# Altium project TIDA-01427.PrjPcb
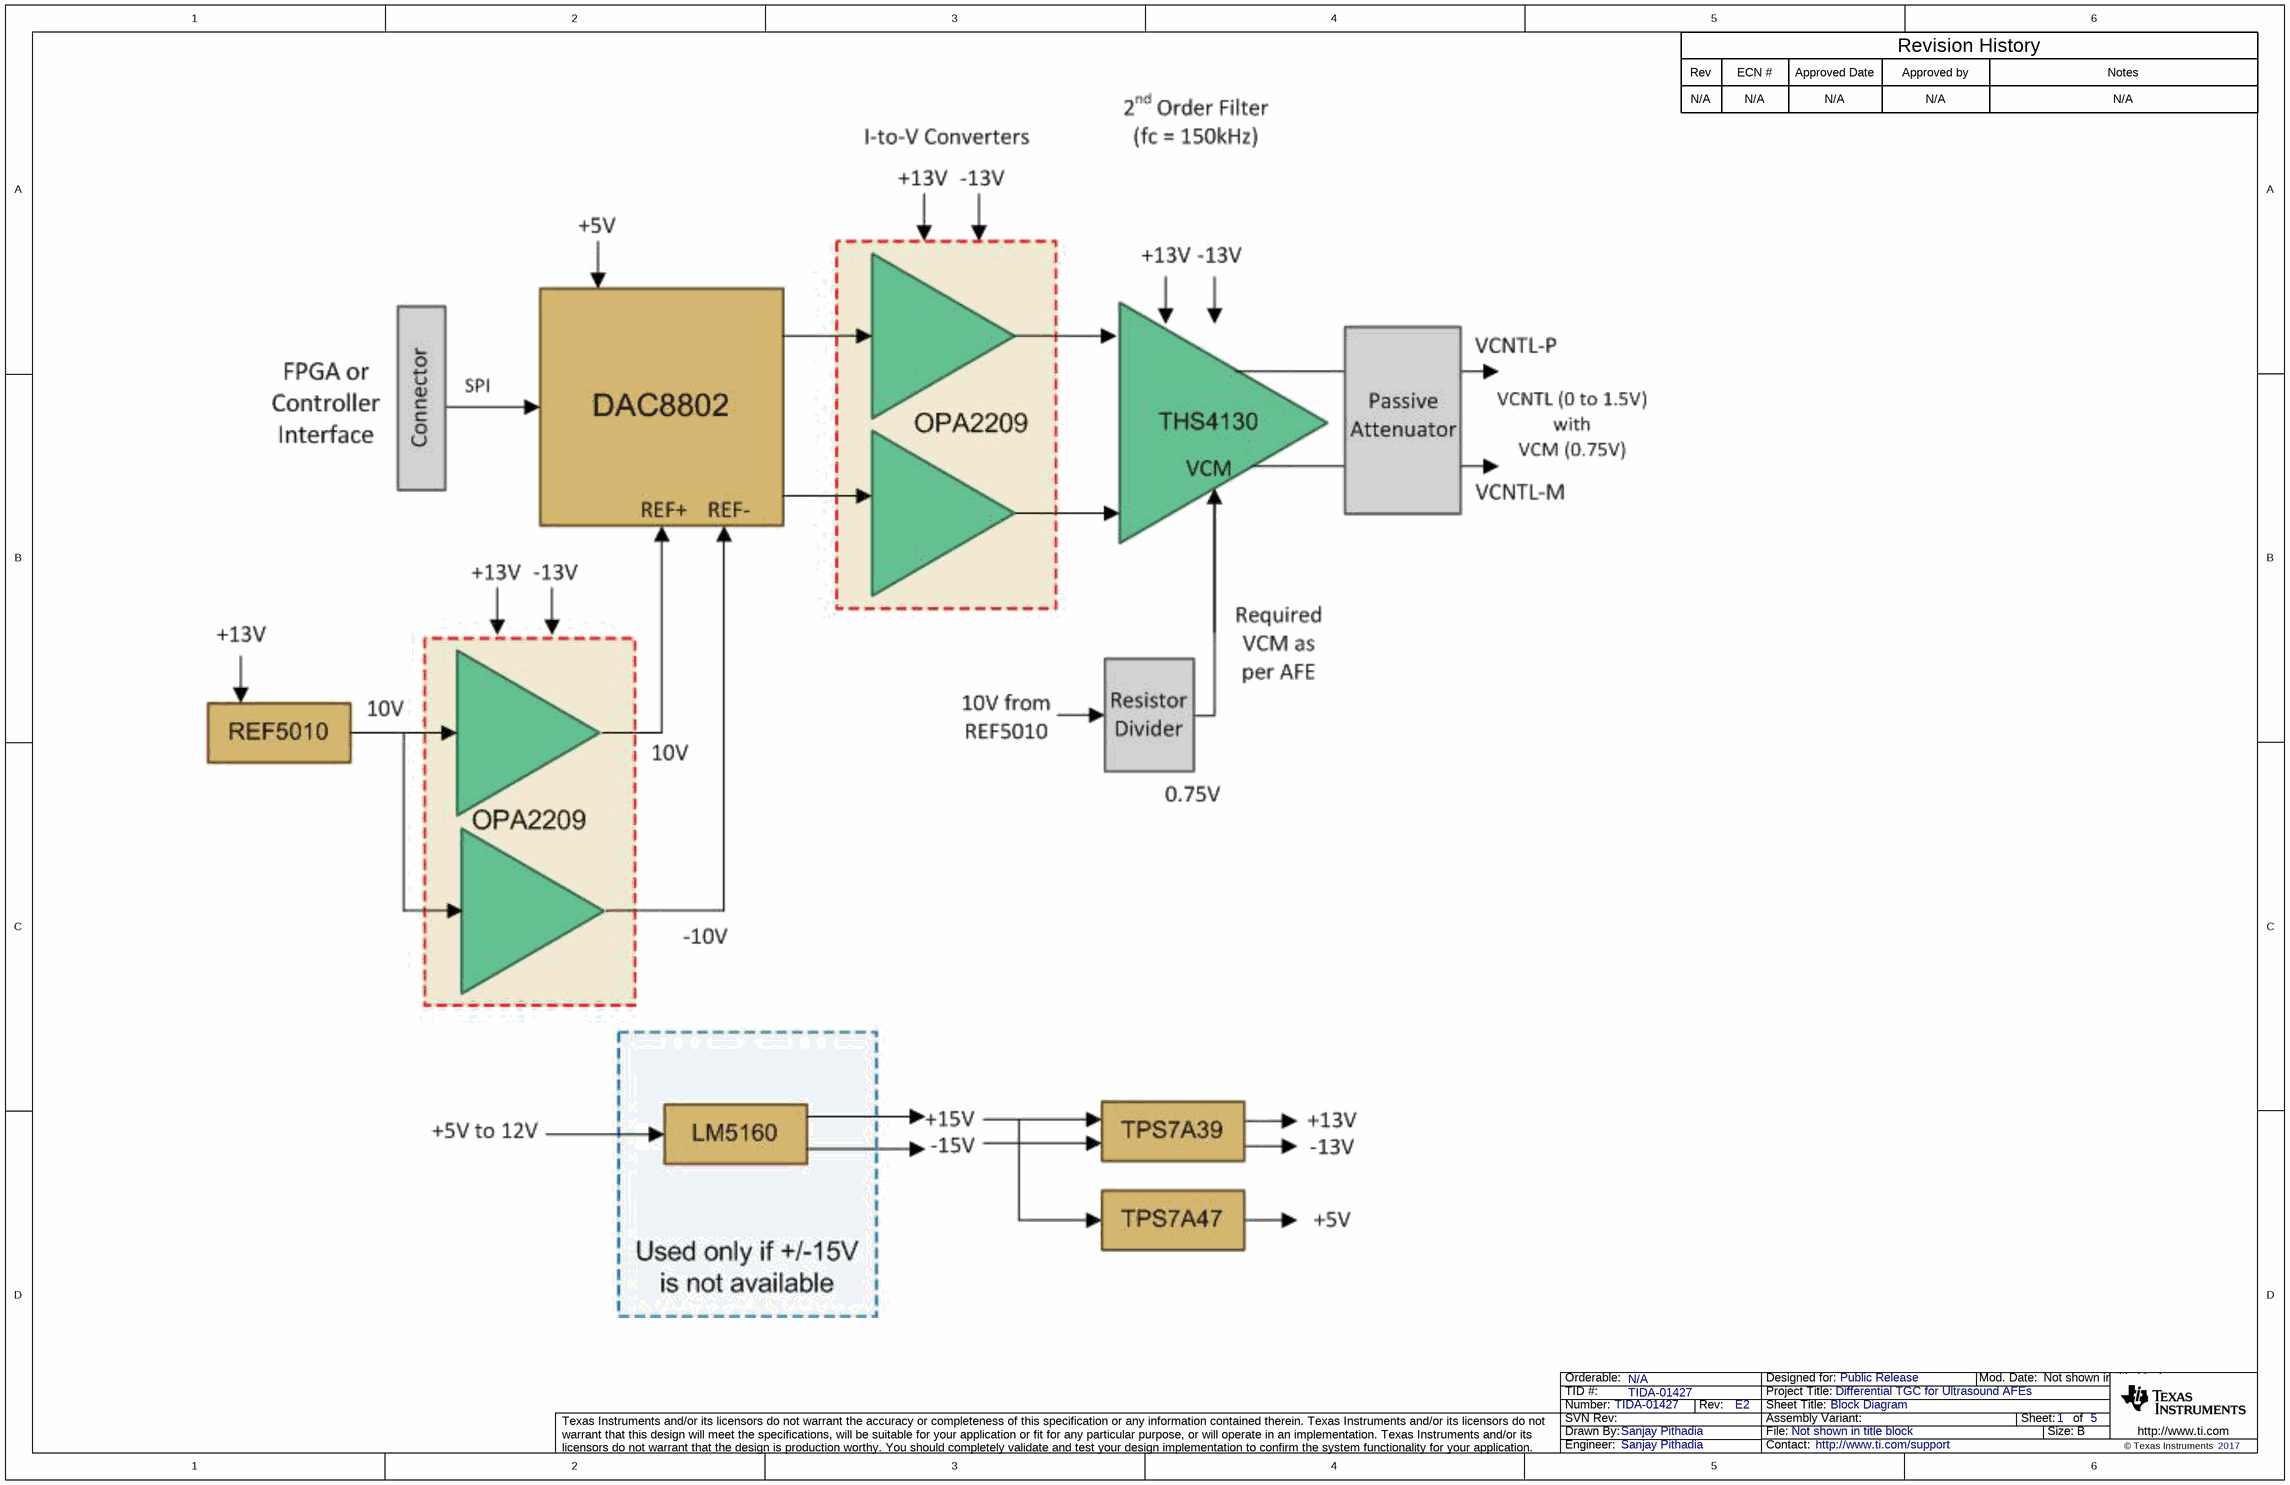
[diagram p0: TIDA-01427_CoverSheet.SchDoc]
CopyrightYear: 2017; EVM_orderable: N/A; PCB_Layout: Akshay Labhe; PCB_Rev: E2; PRJ_Customer: Public Release; PRJ_Engineer: Sanjay Pithadia; PRJ_Number: TIDA-01427; PRJ_Title: Differential TGC for Ultrasound AFEs; SCH_Rev: E2; TechSupport: http://www.ti.com/support; TID: TIDA-01427
5 sheets, 175 parts. Net scope: flat (ports and power ports of the same name join across sheets).
Board file: TIDA-01427_PCB.PcbDoc
Sheets:
  TIDA-01427_CoverSheet.SchDoc
  TIDA-01427_Power_Supply.SchDoc
  TIDA-01427_Reference.SchDoc
  TIDA-01427_DAC_I2V_Filter_Attenuator.SchDoc
  TIDA-01427_Hardware.SchDoc

## Sheet TIDA-01427_CoverSheet.SchDoc: Block Diagram
size 431 x 279 mm; Date: Not shown in title block; ApprovedBy: Not shown in title block; CheckedBy: Not shown in title block; Author: Not shown in title block; CompanyName: Not shown in title block; DrawnBy: Sanjay Pithadia; Engineer: Not shown in title block; Organization: Not shown in title block; Address1: Not shown in title block; Address2: Not shown in title block; Address3: Not shown in title block; Address4: Not shown in title block; DocumentNumber: 1; Revision: Use project parameter SCH_Rev; SheetNumber: 1; SheetTotal: 5; PageSetup: Record=PageOptions¦CenterHorizontal=True¦CenterVertical=True¦PrintScale=1.00¦XCorrection=1.00¦YCorrection=1.00¦PrintKind=0¦BorderSize=5000000¦LeftOffset=0¦BottomOffset=0¦Orientation=2¦PaperLength=1000¦PaperWidth=1000¦Scale=100¦PaperSource=15¦PrintQuality=600¦MediaType=1¦DitherType=10¦PaperKind=Letter¦PrintScaleMode=1

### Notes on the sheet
- Rev
- N/A
- ECN #
- Approved Date
- Approved by
- Revision History
- Notes

## Sheet TIDA-01427_Power_Supply.SchDoc: Power Supply
size 431 x 279 mm; Date: Not shown in title block; ApprovedBy: Not shown in title block; CheckedBy: Not shown in title block; Author: Not shown in title block; CompanyName: Not shown in title block; DrawnBy: Sanjay Pithadia; Engineer: Not shown in title block; Organization: Not shown in title block; Address1: Not shown in title block; Address2: Not shown in title block; Address3: Not shown in title block; Address4: Not shown in title block; DocumentNumber: 1; Revision: Use project parameter SCH_Rev; SheetNumber: 2; SheetTotal: 5; PageSetup: Record=PageOptions¦CenterHorizontal=True¦CenterVertical=True¦PrintScale=1.00¦XCorrection=1.00¦YCorrection=1.00¦PrintKind=0¦BorderSize=5000000¦LeftOffset=0¦BottomOffset=0¦Orientation=2¦PaperLength=1000¦PaperWidth=1000¦Scale=100¦PaperSource=15¦PrintQuality=600¦MediaType=1¦DitherType=10¦PaperKind=Letter¦PrintScaleMode=1
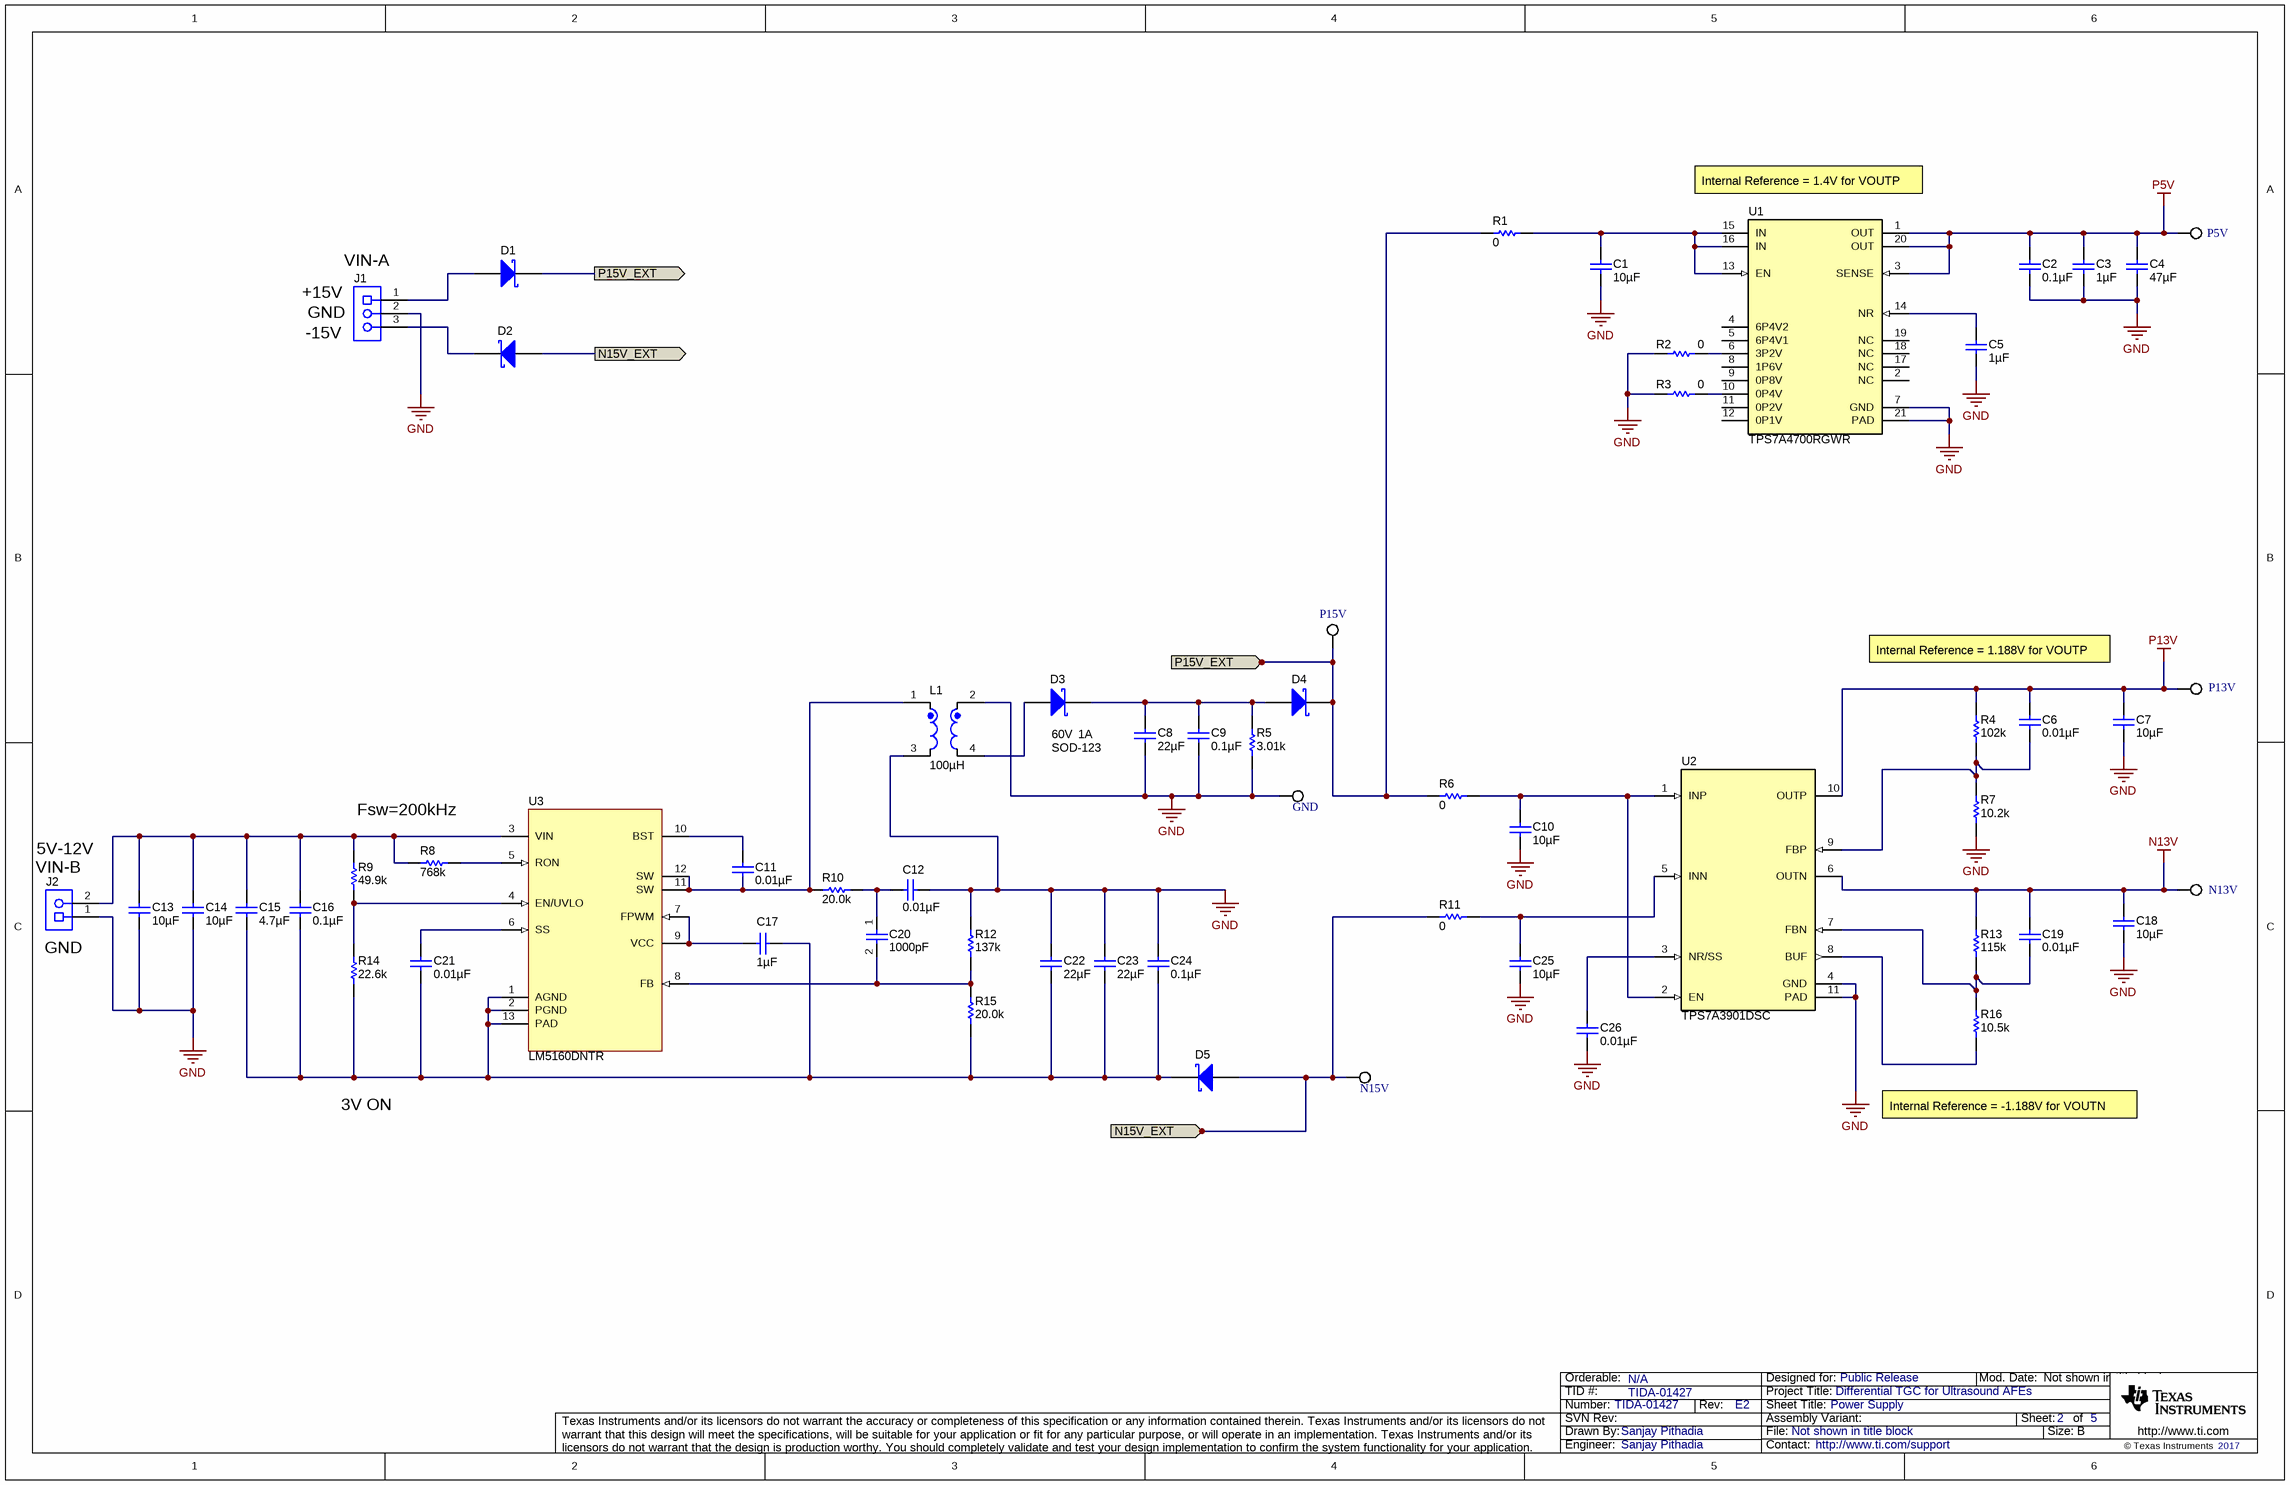
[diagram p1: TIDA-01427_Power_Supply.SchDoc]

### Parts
C1  ValueDisplayed: 10µF  [1210_270]  (hidden comment: GRM32ER71H106KA12L)
C2  ValueDisplayed: 0.1µF  [0603]  (hidden comment: GCM188R71H104KA57D)
C3  ValueDisplayed: 1µF  [0603]  (hidden comment: GRM188R61H105KAALD)
C4  ValueDisplayed: 47µF  [1210_270]  (hidden comment: GRM32EC81C476ME15L)
C5  ValueDisplayed: 1µF  [0603]  (hidden comment: GRM188R61H105KAALD)
C6  ValueDisplayed: 0.01µF  [0603]  (hidden comment: C0603C103J5RACTU)
C7  ValueDisplayed: 10µF  [1210_270]  (hidden comment: GRM32ER71H106KA12L)
C8  ValueDisplayed: 22µF  [1210L]  (hidden comment: GRM32ER71E226KE15L)
C9  ValueDisplayed: 0.1µF  [0603]  (hidden comment: GCM188R71H104KA57D)
C10  ValueDisplayed: 10µF  [1210_270]  (hidden comment: GRM32ER71H106KA12L)
C11  ValueDisplayed: 0.01µF  [0603]  (hidden comment: C0603C103J5RACTU)
C12  ValueDisplayed: 0.01µF  [0603]  (hidden comment: C0603C103J5RACTU)
C13  ValueDisplayed: 10µF  [1210_270]  (hidden comment: GRM32ER71H106KA12L)
C14  ValueDisplayed: 10µF  [1210_270]  (hidden comment: GRM32ER71H106KA12L)
C15  ValueDisplayed: 4.7µF  [1206]  (hidden comment: GRM319R61E475KA12D)
C16  ValueDisplayed: 0.1µF  [0603L]  (hidden comment: C1608X7R1H104K)
C17  ValueDisplayed: 1µF  [0603L]  (hidden comment: C1608X7R1E105K080AB)
C18  ValueDisplayed: 10µF  [1210_270]  (hidden comment: GRM32ER71H106KA12L)
C19  ValueDisplayed: 0.01µF  [0603]  (hidden comment: C0603C103J5RACTU)
C20  ValueDisplayed: 1000pF  [0603]  (hidden comment: GRM188R71H102JA01D)
C21  ValueDisplayed: 0.01µF  [0603]  (hidden comment: C0603C103J5RACTU)
C22  ValueDisplayed: 22µF  [1210L]  (hidden comment: GRM32ER71E226KE15L)
C23  ValueDisplayed: 22µF  [1210L]
C24  ValueDisplayed: 0.1µF  [0603]  (hidden comment: GCM188R71H104KA57D)
C25  ValueDisplayed: 10µF  [1210_270]  (hidden comment: GRM32ER71H106KA12L)
C26  ValueDisplayed: 0.01µF  [0603]  (hidden comment: C0603C103J5RACTU)
D1  DFLS130L-7  [PowerDI123]  (value not drawn)
D2  DFLS130L-7  [PowerDI123]  (value not drawn)
D3  value 60V  Value1: 1A  [SOD-123]  (hidden comment: RB160M-60TR)
D4  DFLS130L-7  [PowerDI123]  (value not drawn)
D5  DFLS130L-7  [PowerDI123]  (value not drawn)
GND  5007  [Keystone5007]  (value not drawn)
J1  ED555/3DS  [TERM_BLK_ED555-3DS]  (value not drawn)
J2  39357-0002  [Molex_39357-0002]  (value not drawn)
L1  ValueDisplayed: 100µH  [SRF1260]  (hidden comment: SRF1260-101M)
N13V  5007  [Keystone5007]  (value not drawn)
N15V  5007  [Keystone5007]  (value not drawn)
P5V  5007  [Keystone5007]  (value not drawn)
P13V  5007  [Keystone5007]  (value not drawn)
P15V  5007  [Keystone5007]  (value not drawn)
R1  ValueDisplayed: 0  [0603]  (hidden comment: CRCW06030000Z0EA)
R2  ValueDisplayed: 0  [0603]  (hidden comment: CRCW06030000Z0EA)
R3  ValueDisplayed: 0  [0603]  (hidden comment: CRCW06030000Z0EA)
R4  ValueDisplayed: 102k  [0603]  (hidden comment: CRCW0603102KFKEA)
R5  ValueDisplayed: 3.01k  [0603L]  (hidden comment: CRCW06033K01FKEA)
R6  ValueDisplayed: 0  [0603]  (hidden comment: CRCW06030000Z0EA)
R7  ValueDisplayed: 10.2k  [0603]  (hidden comment: RC0603FR-0710K2L)
R8  ValueDisplayed: 768k  [0603L]  (hidden comment: CRCW0603768KFKEA)
R9  ValueDisplayed: 49.9k  [0603L]  (hidden comment: CRCW060349K9FKEA)
R10  ValueDisplayed: 20.0k  [0603L]  (hidden comment: CRCW060320K0FKEA)
R11  ValueDisplayed: 0  [0603]  (hidden comment: CRCW06030000Z0EA)
R12  ValueDisplayed: 137k  [0603]  (hidden comment: CRCW0603137KFKEA)
R13  ValueDisplayed: 115k  [0603]  (hidden comment: CRCW0603115KFKEA)
R14  ValueDisplayed: 22.6k  [0603L]  (hidden comment: CRCW060322K6FKEA)
R15  ValueDisplayed: 20.0k  [0603L]  (hidden comment: CRCW060320K0FKEA)
R16  ValueDisplayed: 10.5k  [0603]  (hidden comment: RC0603FR-0710K5L)
U1  TPS7A4700RGWR  [RGW0020A]
U2  TPS7A3901DSC  [DSC0010J]
U3  LM5160DNTR  [DNT0012B]

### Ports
N15V_EXT (in), N15V_EXT (out), P15V_EXT (in), P15V_EXT (out)

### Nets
GND: C1.2 C2.2 C3.2 C4.2 C5.2 C7.2 C8.2 C9.2 C10.2 C12.2 C13.2 C14.2 C18.2 C22.1 C23.1 C24.1 C25.2 C26.1 GND.1 J1.2 J2.1 L1.2 L1.3 R2.1 R3.1 R5.1 R7.1 R12.2 U1.7(GND) U1.21(PAD) U2.4(GND) U2.11(PAD)
N13V: C18.1 C19.2 N13V.1 R13.2 U2.6(OUTN)
P5V: C2.1 C3.1 C4.1 P5V.1 U1.1(OUT) U1.3(SENSE) U1.20(OUT)
P13V: C6.2 C7.1 P13V.1 R4.2 U2.10(OUTP)
N15V_EXT: D2.2(A) D5.2(A) N15V.1 R11.2 ; port N15V_EXT
P15V_EXT: D1.1(K) D4.1(K) P15V.1 R1.2 R6.2 ; port P15V_EXT
NetC1_1: C1.1 R1.1 U1.13(EN) U1.15(IN) U1.16(IN)
NetC5_1: C5.1 U1.14(NR)
NetC6_1: C6.1 R4.1 R7.2 U2.9(FBP)
NetC8_1: C8.1 C9.1 D3.1(K) D4.2(A) R5.2
NetC10_1: C10.1 R6.1 U2.1(INP) U2.2(EN)
NetC11_1: C11.1 U3.10(BST)
NetC11_2: C11.2 L1.1 R10.1 U3.11(SW) U3.12(SW)
NetC12_1: C12.1 C20.1 R10.2
NetC13_1: C13.1 C14.1 C15.1 C16.1 J2.2 R8.1 R9.2 U3.3(VIN)
NetC15_2: C15.2 C16.2 C17.1 C21.2 C22.2 C23.2 C24.2 D5.1(K) R14.1 R15.1 U3.1(AGND) U3.2(PGND) U3.13(PAD)
NetC17_2: C17.2 U3.7(FPWM) U3.9(VCC)
NetC19_1: C19.1 R13.1 R16.2 U2.7(FBN)
NetC20_2: C20.2 R12.1 R15.2 U3.8(FB)
NetC21_1: C21.1 U3.6(SS)
NetC25_1: C25.1 R11.1 U2.5(INN)
NetC26_2: C26.2 U2.3(NR/SS)
NetD1_2: D1.2(A) J1.1
NetD2_1: D2.1(K) J1.3
NetD3_2: D3.2(A) L1.4
NetR2_2: R2.2 U1.6(3P2V)
NetR3_2: R3.2 U1.10(0P4V)
NetR8_2: R8.2 U3.5(RON)
NetR9_1: R9.1 R14.2 U3.4(EN/UVLO)
NetR16_1: R16.1 U2.8(BUF)

Not connected (* = marked no-connect by the designer): U1 2(NC) 4(6P4V2) 5(6P4V1) 8(1P6V) 9(0P8V) 11(0P2V) 12(0P1V) 17(NC) 18(NC) 19(NC)

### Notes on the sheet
- (near U1) Internal Reference = 1.4V for VOUTP
- (near J1) +15V
- (near J1) VIN-A
- (near J1) -15V
- (near J1) GND
- Internal Reference = 1.188V for VOUTP
- Fsw=200kHz
- (near J2) VIN-B
- 5V-12V
- (near J2) GND
- 3V ON
- Internal Reference = -1.188V for VOUTN

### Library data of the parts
C1 C7 C10 C13 C14 C18 C25 = GRM32ER71H106KA12L: CAP, CERM, 10 µF, 50 V, +/- 10%, X7R, 1210; Manufacturer: MuRata; Polarized: N; CompType: Capacitor; Value: 10uF; U/M: EA; Cap_F: 0.00001; Tolerance_%: 10; Value1: Unknown; VDC_V: 50; Value2: 50V; TaMin_C: -55; TaMax_C: 125; Cap_Case: 1210; SizeArea_mm2: 8; SizeAreaWB_mm2: 14.7; SizeX_mm: 3.2; SizeY_mm: 2.5; SizeZ_mm: 2.7; AEC Category: Q200
C2 C9 C24 = GCM188R71H104KA57D: CAP, CERM, 0.1 µF, 50 V, +/- 10%, X7R, 0603; Manufacturer: MuRata; Polarized: N; CompType: Capacitor; Value: 0.1uF; U/M: EA; Cap_F: 0.0000001; Tolerance_%: 10; ESR_ohm: 0.02; Value1: 0.02 ohm; VDC_V: 50; Value2: 50V; IRMS_A: 1.84; TaMin_C: -55; TaMax_C: 125; SizeArea_mm2: 1.28; SizeAreaWB_mm2: 4.68; SizeX_mm: 1.6; SizeY_mm: 0.8; SizeZ_mm: 1; AEC Category: Q200
C3 C5 = GRM188R61H105KAALD: CAP, CERM, 1 µF, 50 V, +/- 10%, X5R, 0603; Manufacturer: MuRata; Polarized: N; CompType: Capacitor; Value: 1uF; U/M: EA; Cap_F: 0.000001; Tolerance_%: 10; Value1: Unknown; VDC_V: 50; Value2: 50V; TaMin_C: -55; TaMax_C: 85; SizeArea_mm2: 1.28; SizeAreaWB_mm2: 4.68; SizeX_mm: 1.6; SizeY_mm: 0.8; SizeZ_mm: 1; AEC Category: Q200
C4 = GRM32EC81C476ME15L: CAP, CERM, 47 µF, 16 V, +/- 20%, X6S, 1210; Manufacturer: MuRata; Polarized: N; CompType: Capacitor; Value: 47uF; U/M: EA; Cap_F: 0.000047; Tolerance_%: 20; Value1: Unknown; VDC_V: 16; Value2: 16V; TaMin_C: -55; TaMax_C: 105; Cap_Case: 1210; SizeArea_mm2: 8; SizeAreaWB_mm2: 14.7; SizeX_mm: 3.2; SizeY_mm: 2.5; SizeZ_mm: 2.7; AEC Category: Q200
C6 C11 C12 C19 C21 C26 = C0603C103J5RACTU: CAP, CERM, 0.01 µF, 50 V, +/- 5%, X7R, 0603; Manufacturer: Kemet; Polarized: N; CompType: Capacitor; Value: 0.01uF; U/M: EA; Cap_F: 0.00000001; Tolerance_%: 5; Value1: Unknown; VDC_V: 50; Value2: 50V; TaMin_C: -55; TaMax_C: 125; SizeArea_mm2: 1.28; SizeAreaWB_mm2: 4.68; SizeX_mm: 1.6; SizeY_mm: 0.8; SizeZ_mm: 1; AEC Category: Q200
C8 C22 C23 = GRM32ER71E226KE15L: CAP, CERM, 22uF, 25V, +/-10%, X7R, 1210; Manufacturer: MuRata; Polarized: N; CompType: Capacitor; U/M: EA; Cap_F: 0.000022; Tolerance_%: 10; Value1: Unknown; VDC_V: 25; TaMin_C: -55; TaMax_C: 125; Cap_Case: 1210
C15 = GRM319R61E475KA12D: CAP, CERM, 4.7 µF, 25 V, +/- 10%, X5R, 1206; Manufacturer: MuRata; Polarized: N; CompType: Capacitor; Value: 4.7uF; U/M: EA; Cap_F: 0.0000047; Tolerance_%: 10; ESR_ohm: 0.006; Value1: 0.006 ohm; VDC_V: 25; Value2: 25V; TaMin_C: -55; TaMax_C: 85; SizeArea_mm2: 5.12; SizeAreaWB_mm2: 10.92; SizeX_mm: 3.2; SizeY_mm: 1.6; SizeZ_mm: 1.35; AEC Category: Q200
C16 = C1608X7R1H104K: CAP, CERM, 0.1uF, 50V, +/-10%, X7R, 0603; Manufacturer: TDK; Polarized: N; CompType: Capacitor; U/M: EA; Cap_F: 0.0000001; Tolerance_%: 10; ESR_Ohm: 0.017; Value1: 0.017 ohm; VDC_V: 50; TaMin_C: -55; TaMax_C: 125; Cap_Case: 0603
C17 = C1608X7R1E105K080AB: CAP, CERM, 1uF, 25V, +/-10%, X7R, 0603; Manufacturer: TDK; Polarized: N; CompType: Capacitor; U/M: EA; Cap_F: 0.000001; Tolerance_%: 10; Value1: Unknown; VDC_V: 25; TaMin_C: -55; TaMax_C: 125; Cap_Case: 0603
C20 = GRM188R71H102JA01D: CAP, CERM, 1000 pF, 50 V, +/- 5%, X7R, 0603; Manufacturer: MuRata; Polarized: N; CompType: Capacitor; Value: 1000pF; U/M: EA; Cap_F: 0.000000001; Tolerance_%: 5; Value1: Unknown; VDC_V: 50; Value2: 50V; TaMin_C: -55; TaMax_C: 125; SizeArea_mm2: 1.28; SizeAreaWB_mm2: 4.68; SizeX_mm: 1.6; SizeY_mm: 0.8; SizeZ_mm: 1; AEC Category: Q200
D1 D2 D4 D5 = DFLS130L-7: Diode, Schottky, 30 V, 1 A, PowerDI123; Manufacturer: Diodes Inc.; U/M: EA; Vf_V: 0.31; Value: 30V; Value1: 1A; Value2: 0.31V; Io_A: 1; Vr_V: 30; TJmax_C: 125; SizeAreaWB_mm2: 13.066; SizeArea_mm2: 6.586; SizeX_mm: 3.7; SizeY_mm: 1.78; SizeZ_mm: 0.98; AEC Category: Q101; AEC Qualified: N
D3 = RB160M-60TR: Diode, Schottky, 60 V, 1 A, SOD-123; Manufacturer: Rohm; U/M: EA; Vf_V: 0.55; Value2: 0.55V; Io_A: 1; Vr_V: 60; TJmax_C: 150
GND N13V N15V P5V P13V P15V = 5007: Test Point, Compact, White, TH; Manufacturer: Keystone; CompType: Test Point Loop; ContactFinish: Silver
J1 = ED555/3DS: Terminal Block, 3.5mm Pitch, 3x1, TH; Manufacturer: On-Shore Technology; SymbolCreator: a0412235; Pitch_mm: 3.5; Gender: Female; Shrouded: N; Row_Count: 1; ContactFinish: Brass; Current_A: 6; Voltage_V: 150; Cert_CULUS: Y
J2 = 39357-0002: Terminal Block, 3.5 mm, 2x1, Tin, TH; Manufacturer: Molex; SymbolCreator: a0412235
L1 = SRF1260-101M: Inductor, Drum Core, Ferrite, 100 µH, 1.78 A, 0.171 ohm, SMD; Manufacturer: Bourns; SymbolCreator: Altium; Ind_H: 100.0E-6; Value: 100uH; Imax_A: 1.78; Irms: 1.78A @ 40C rise; Isat: 2.2A @ 30% inductance drop; DCR_ohm: 0.171; Value2: 1.78A; SizeAreaWB_mm2: 210.25; SizeArea_mm2: 156.25; SizeX_mm: 12.5; SizeZ_mm: 6; AEC Category: Q200
R1-R3 R6 R11 = CRCW06030000Z0EA: RES, 0, 5%, 0.1 W, 0603; Manufacturer: Vishay-Dale; CompType: Resistor; Value: 0; Value_Code: 0000; Tolerance_%: 5; Power_W: 0.1; Value2: 0.1W; VDC_V: 75; TempCo: 200 ppm/C; SizeArea_mm2: 1.28; SizeX_mm: 1.6; SizeY_mm: 0.8; SizeZ_mm: 1; EIA_Code: E24; U/M: EA; AEC Category: Q200
R4 = CRCW0603102KFKEA: RES, 102 k, 1%, 0.1 W, 0603; Manufacturer: Vishay-Dale; CompType: Resistor; Value: 102k; Res_ohm: 102000; Tolerance_%: 1; Power_W: 0.1; Value2: 0.1W; VDC_V: 75; TempCo: 100 ppm/C; SizeArea_mm2: 1.28; SizeX_mm: 1.6; SizeY_mm: 0.8; EIA_Code: E96; U/M: EA; AEC Category: Q200
R5 = CRCW06033K01FKEA: RES, 3.01 k, 1%, 0.1 W, 0603; Manufacturer: Vishay-Dale; CompType: Resistor; Tolerance_%: 1; VDC_V: 75; Power_W: 0.1; Res_ohm: 3010; Value: 3.01k; Value_Code: 3k01; Value2: 0.1W; EIA_Code: E96; TempCo: 100 ppm/C; U/M: EA; AEC Category: Q200
R7 = RC0603FR-0710K2L: RES, 10.2 k, 1%, 0.1 W, 0603; Manufacturer: Yageo America; CompType: Resistor; Value: 10.2k; Res_ohm: 10200; Value_Code: 10k2; Tolerance_%: 1; Power_W: 0.1; Value2: 0.1W; VDC_V: 150; TempCo: 200 ppm/C; SizeArea_mm2: 1.28; SizeX_mm: 1.6; SizeY_mm: 0.8; EIA_Code: E96; U/M: EA; AEC Category: Q200
R8 = CRCW0603768KFKEA: RES, 768 k, 1%, 0.1 W, 0603; Manufacturer: Vishay-Dale; CompType: Resistor; Value: 768k; Res_ohm: 768000; Tolerance_%: 1; Power_W: 0.1; Value2: 0.1W; VDC_V: 75; TempCo: 100 ppm/C; EIA_Code: E96; U/M: EA; AEC Category: Q200
R9 = CRCW060349K9FKEA: RES, 49.9 k, 1%, 0.1 W, 0603; Manufacturer: Vishay-Dale; CompType: Resistor; Tolerance_%: 1; VDC_V: 75; Power_W: 0.1; Res_ohm: 49900; Value: 49.9k; Value_Code: 49k9; Value2: 0.1W; EIA_Code: E96; TempCo: 100 ppm/C; U/M: EA; AEC Category: Q200
R10 = CRCW060320K0FKEA: RES, 20.0 k, 1%, 0.1 W, 0603; Manufacturer: Vishay-Dale; CompType: Resistor; Tolerance_%: 1; VDC_V: 75; Power_W: 0.1; Res_ohm: 20000; Value: 20.0k; Value_Code: 20k0; Value2: 0.1W; EIA_Code: E96; TempCo: 100 ppm/C; U/M: EA
R12 = CRCW0603137KFKEA: RES, 137 k, 1%, 0.1 W, 0603; Manufacturer: Vishay-Dale; CompType: Resistor; Value: 137k; Res_ohm: 137000; Tolerance_%: 1; Power_W: 0.1; Value2: 0.1W; VDC_V: 75; TempCo: 100 ppm/C; SizeArea_mm2: 1.28; SizeX_mm: 1.6; SizeY_mm: 0.8; EIA_Code: E96; U/M: EA; AEC Category: Q200
R13 = CRCW0603115KFKEA: RES, 115 k, 1%, 0.1 W, 0603; Manufacturer: Vishay-Dale; CompType: Resistor; Value: 115k; Res_ohm: 115000; Tolerance_%: 1; Power_W: 0.1; Value2: 0.1W; VDC_V: 75; TempCo: 100 ppm/C; SizeArea_mm2: 1.28; SizeX_mm: 1.6; SizeY_mm: 0.8; EIA_Code: E96; U/M: EA; AEC Category: Q200
R14 = CRCW060322K6FKEA: RES, 22.6 k, 1%, 0.1 W, 0603; Manufacturer: Vishay-Dale; CompType: Resistor; Tolerance_%: 1; VDC_V: 75; Power_W: 0.1; Res_ohm: 22600; Value: 22.6k; Value_Code: 22k6; Value2: 0.1W; EIA_Code: E96; TempCo: 100 ppm/C; U/M: EA; AEC Category: Q200
R15 = CRCW060320K0FKEA: RES, 20.0 k, 1%, 0.1 W, 0603; Manufacturer: Vishay-Dale; CompType: Resistor; Res_ohm: 20000; Value_Code: 20k0; Tolerance_%: 1; Power_W: 0.1; Value2: 0.1W; VDC_V: 75; TempCo: 100 ppm/C; EIA_Code: E96; U/M: EA; Value: 20.0k
R16 = RC0603FR-0710K5L: RES, 10.5 k, 1%, 0.1 W, 0603; Manufacturer: Yageo America; CompType: Resistor; Value: 10.5k; Res_ohm: 10500; Value_Code: 10k5; Tolerance_%: 1; Power_W: 0.1; Value2: 0.1W; VDC_V: 150; TempCo: 200 ppm/C; SizeArea_mm2: 1.28; SizeX_mm: 1.6; SizeY_mm: 0.8; EIA_Code: E96; U/M: EA; AEC Category: Q200
U1 = TPS7A4700RGWR: 36-V, 1-A, 4.17-uVRMS, RF LDO Voltage Regulator, RGW0020A (VQFN-20); Alternate PartNumber: TPS7A4700RGWT; Manufacturer: Texas Instruments; SymbolCreator: a0412235; SizeArea_mm2: 25; SizeAreaWB_mm2: 49; SizeX_mm: 5; SizeZ_mm: 1; CompType: IC; U/M: EA
U2 = TPS7A3901DSC: Wide-VIN (+/-33 V), 150-mA, Spilt-Rail Output, Positive and Negative LDO Voltage Regulator with Startup Tracking, DSC0010J (WSON-10); Manufacturer: Texas Instruments; SymbolCreator: Altium; SizeArea_mm2: 9; SizeAreaWB_mm2: 16; SizeX_mm: 3; SizeZ_mm: 0.8; CompType: IC; U/M: EA
U3 = LM5160DNTR: Wide Input 65V, 1.5A Synchronous Step-Down DC-DC Converter, DNT0012B; Alternate PartNumber: LM5160DNTT; Manufacturer: Texas Instruments; SymbolCreator: a0411947; CompType: IC; U/M: EA

## Sheet TIDA-01427_Reference.SchDoc: Reference Generation
size 431 x 279 mm; Date: Not shown in title block; ApprovedBy: Not shown in title block; CheckedBy: Not shown in title block; Author: Not shown in title block; CompanyName: Not shown in title block; DrawnBy: Sanjay Pithadia; Engineer: Not shown in title block; Organization: Not shown in title block; Address1: Not shown in title block; Address2: Not shown in title block; Address3: Not shown in title block; Address4: Not shown in title block; DocumentNumber: 1; Revision: Use project parameter SCH_Rev; SheetNumber: 3; SheetTotal: 5; PageSetup: Record=PageOptions¦CenterHorizontal=True¦CenterVertical=True¦PrintScale=1.00¦XCorrection=1.00¦YCorrection=1.00¦PrintKind=0¦BorderSize=5000000¦LeftOffset=0¦BottomOffset=0¦Orientation=2¦PaperLength=1000¦PaperWidth=1000¦Scale=100¦PaperSource=15¦PrintQuality=600¦MediaType=1¦DitherType=10¦PaperKind=Letter¦PrintScaleMode=1
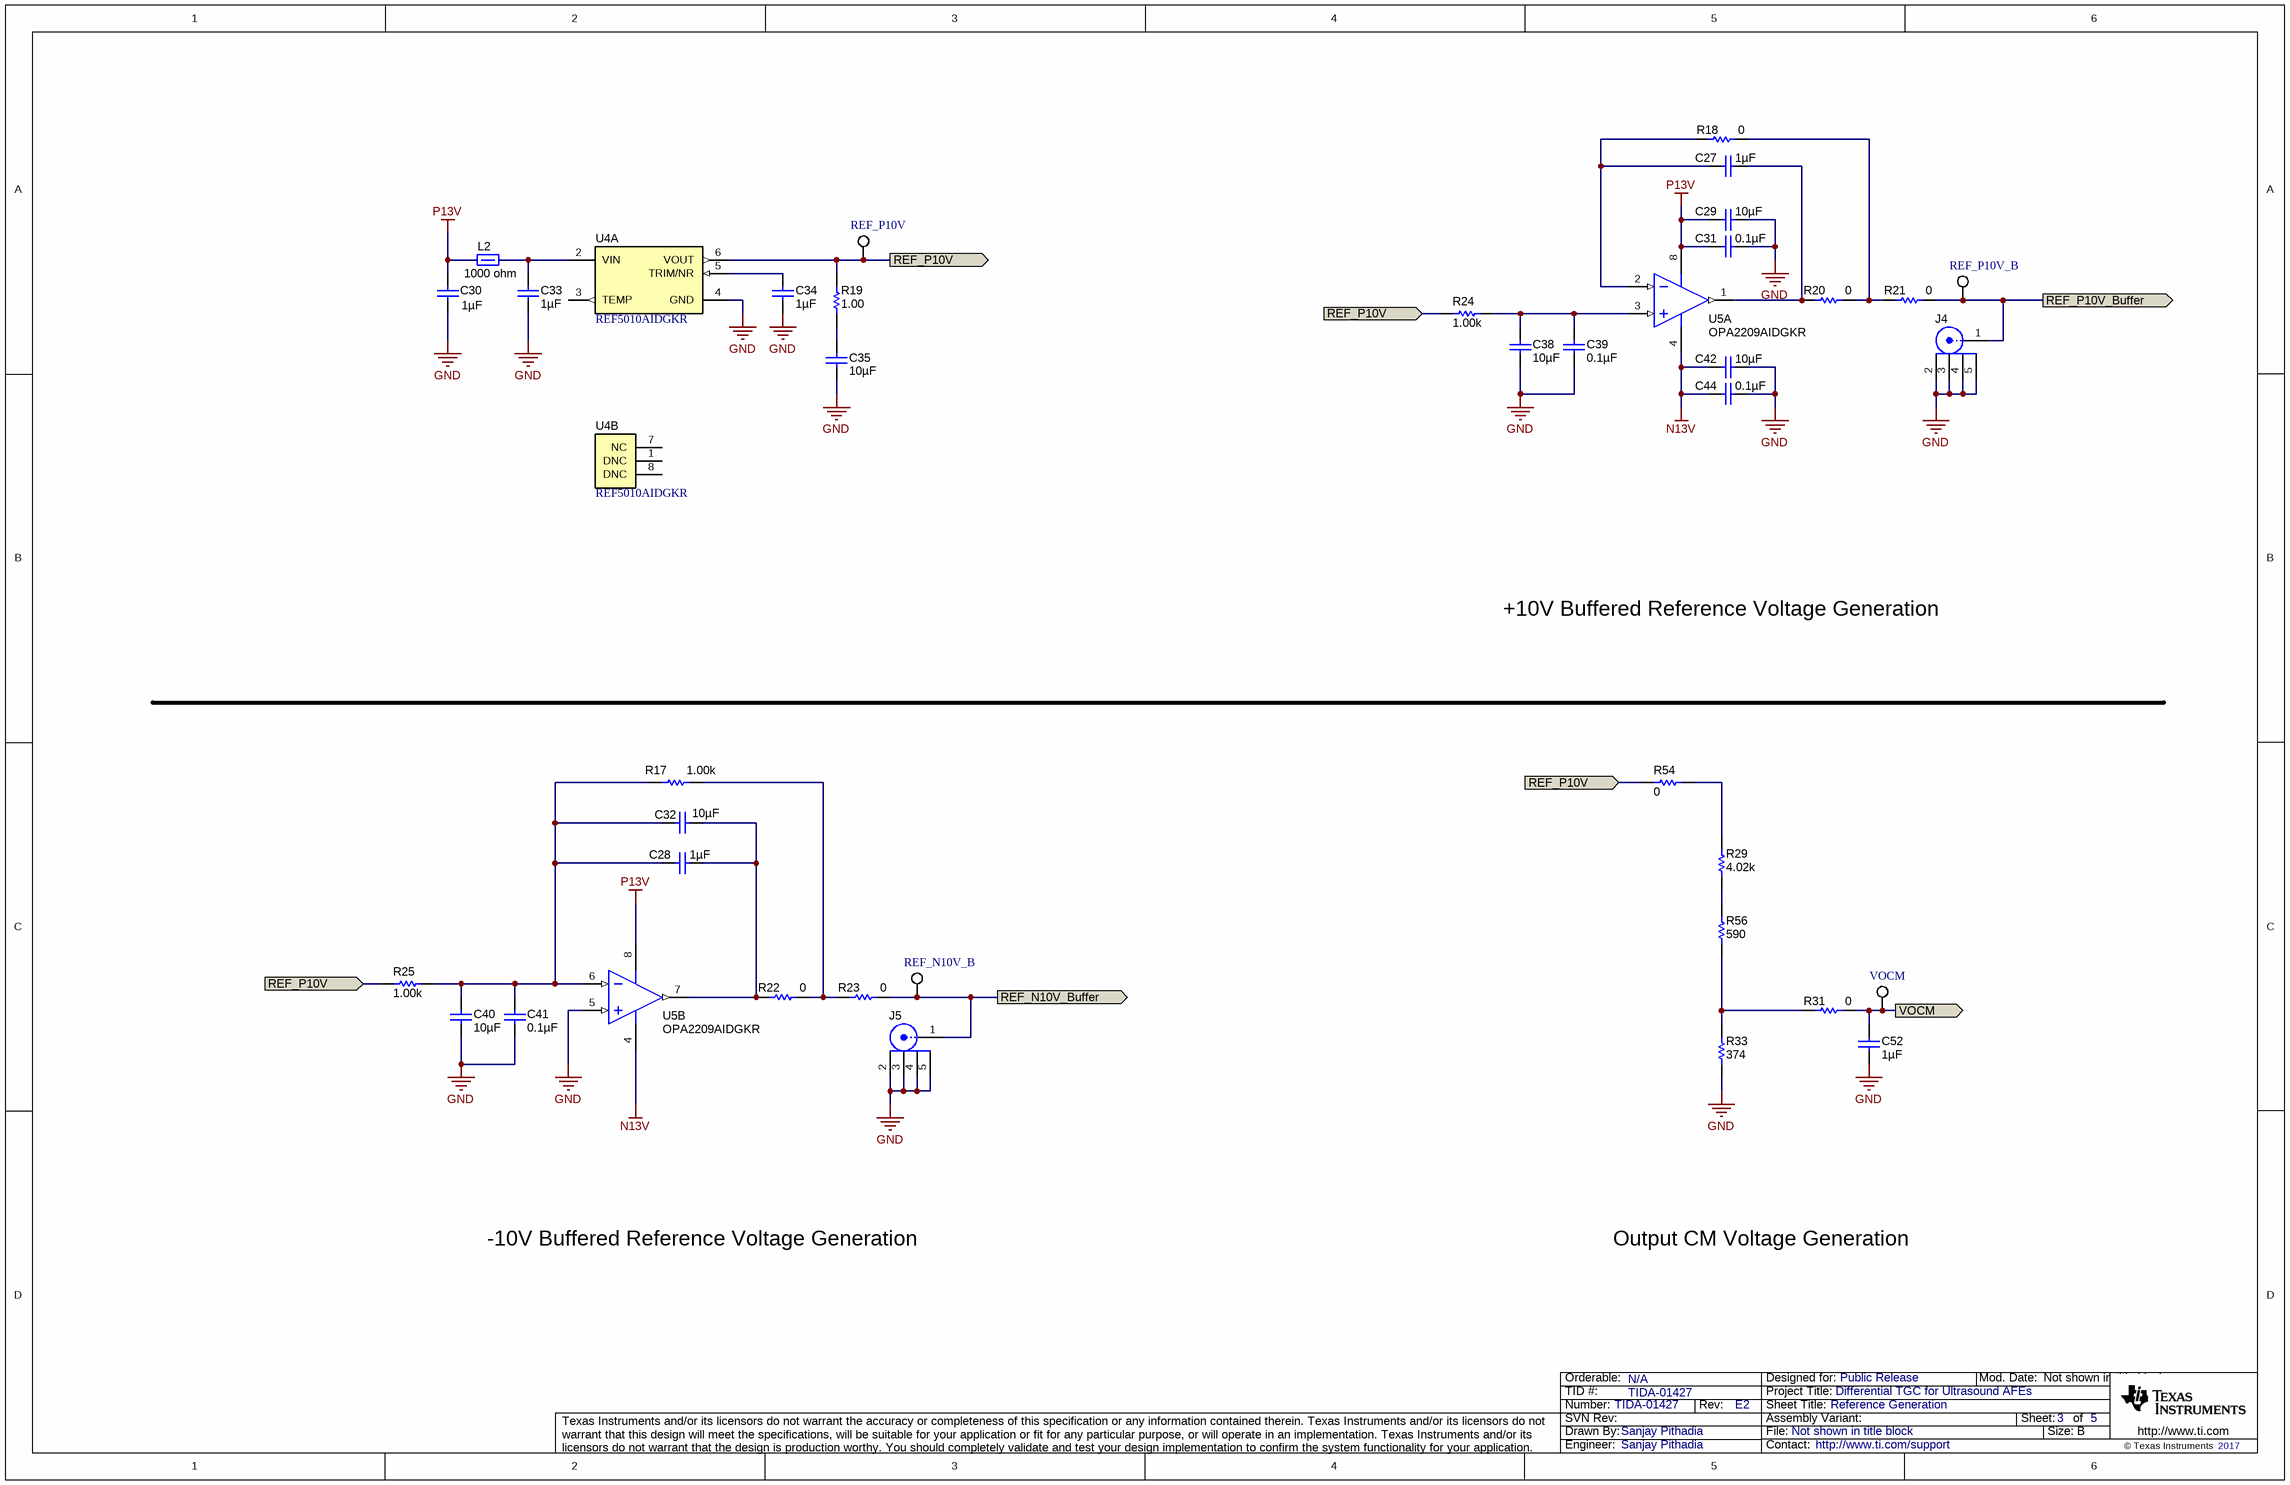
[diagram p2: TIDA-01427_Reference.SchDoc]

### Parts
C27  ValueDisplayed: 1µF  [0603]  (hidden comment: GRM188R71E105KA12D)
C28  ValueDisplayed: 1µF  [0603]  (hidden comment: GRM188R71E105KA12D)
C29  ValueDisplayed: 10µF  [0603]  (hidden comment: C1608X5R1E106M080AC)
C30  ValueDisplayed: 1µF  [0603]  (hidden comment: GRM188R71E105KA12D)
C31  ValueDisplayed: 0.1µF  [0603]  (hidden comment: C0603C104J3RACTU)
C32  ValueDisplayed: 10µF  [0603]  (hidden comment: C1608X5R1E106M080AC)
C33  ValueDisplayed: 1µF  [0603]  (hidden comment: GRM188R71E105KA12D)
C34  ValueDisplayed: 1µF  [0603]  (hidden comment: GRM188R71E105KA12D)
C35  ValueDisplayed: 10µF  [0603]  (hidden comment: C1608X5R1E106M080AC)
C38  ValueDisplayed: 10µF  [0603]  (hidden comment: C1608X5R1E106M080AC)
C39  ValueDisplayed: 0.1µF  [0603]  (hidden comment: C0603C104J3RACTU)
C40  ValueDisplayed: 10µF  [0603]  (hidden comment: C1608X5R1E106M080AC)
C41  ValueDisplayed: 0.1µF  [0603]  (hidden comment: C0603C104J3RACTU)
C42  ValueDisplayed: 10µF  [0603]  (hidden comment: C1608X5R1E106M080AC)
C44  ValueDisplayed: 0.1µF  [0603]  (hidden comment: C0603C104J3RACTU)
C52  ValueDisplayed: 1µF  [0603]  (hidden comment: GRM188R71E105KA12D)
J4  901-144-8RFX  [Amphenol_901-144-8RFX]  (value not drawn)
J5  901-144-8RFX  [Amphenol_901-144-8RFX]  (value not drawn)
L2  value 1000 ohm  [0805_HV]  (hidden comment: MPZ2012S102AT000)
R17  ValueDisplayed: 1.00k  [0603]  (hidden comment: RT0603DRE071KL)
R18  ValueDisplayed: 0  [0603]  (hidden comment: CRCW06030000Z0EA)
R19  ValueDisplayed: 1.00  [0603]  (hidden comment: CRCW06031R00FKEA)
R20  ValueDisplayed: 0  [0603]  (hidden comment: CRCW06030000Z0EA)
R21  ValueDisplayed: 0  [0603]  (hidden comment: CRCW06030000Z0EA)
R22  ValueDisplayed: 0  [0603]  (hidden comment: CRCW06030000Z0EA)
R23  ValueDisplayed: 0  [0603]  (hidden comment: CRCW06030000Z0EA)
R24  ValueDisplayed: 1.00k  [0603]  (hidden comment: RT0603DRE071KL)
R25  ValueDisplayed: 1.00k  [0603]  (hidden comment: RT0603DRE071KL)
R29  ValueDisplayed: 4.02k  [0603]  (hidden comment: RT0603DRE074K02L)
R31  ValueDisplayed: 0  [0603]  (hidden comment: CRCW06030000Z0EA)
R33  ValueDisplayed: 374  [0603]  (hidden comment: RT0603DRE07374RL)
R54  ValueDisplayed: 0  [0603]  (hidden comment: CRCW06030000Z0EA)
R56  ValueDisplayed: 590  [0603]  (hidden comment: RT0603DRE07590RL)
REF_N10V_B  5007  [Keystone5007]  (value not drawn)
REF_P10V  5007  [Keystone5007]  (value not drawn)
REF_P10V_B  5007  [Keystone5007]  (value not drawn)
U4  REF5010AIDGKR  [DGK0008A_N]  (parts A,B of 2)
U5  OPA2209AIDGKR  [DGK0008A_N]  (parts A,B of 2)
VOCM  5007  [Keystone5007]  (value not drawn)

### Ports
REF_N10V_Buffer (out), REF_P10V (in), REF_P10V (out), REF_P10V_Buffer (out), VOCM (out)

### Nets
GND: C29.2 C30.2 C31.1 C33.2 C34.2 C35.1 C38.2 C39.2 C40.2 C41.2 C42.2 C44.1 C52.1 J4.2 J4.3 J4.4 J4.5 J5.2 J5.3 J5.4 J5.5 R33.1 U4.4(GND) U5.5(IN_B+)
N13V: C42.1 C44.2 U5.4(V-)
P13V: C29.1 C30.1 C31.2 L2.2 U5.8(V+)
REF_N10V_Buffer: J5.1 R23.2 REF_N10V_B.1 ; port REF_N10V_Buffer
REF_P10V: R19.2 R24.1 R25.1 R54.2 REF_P10V.1 U4.6(VOUT) ; port REF_P10V
REF_P10V_Buffer: J4.1 R21.2 REF_P10V_B.1 ; port REF_P10V_Buffer
VOCM: C52.2 R31.2 VOCM.1 ; port VOCM
NetC27_1: C27.1 R18.1 U5.2(IN_A-)
NetC27_2: C27.2 R20.1 U5.1(OUT_A)
NetC28_1: C28.1 C32.1 C40.1 C41.1 R17.1 R25.2 U5.6(IN_B-)
NetC28_2: C28.2 C32.2 R22.1 U5.7(OUT_B)
NetC33_1: C33.1 L2.1 U4.2(VIN)
NetC34_1: C34.1 U4.5(TRIM/NR)
NetC35_2: C35.2 R19.1
NetC38_1: C38.1 C39.1 R24.2 U5.3(IN_A+)
NetR17_2: R17.2 R22.2 R23.1
NetR18_2: R18.2 R20.2 R21.1
NetR29_1: R29.1 R56.2
NetR29_2: R29.2 R54.1
NetR31_1: R31.1 R33.2 R56.1

Not connected (* = marked no-connect by the designer): U4 1(DNC) 3(TEMP) 7(NC) 8(DNC)

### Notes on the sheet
- +10V Buffered Reference Voltage Generation
- -10V Buffered Reference Voltage Generation
- Output CM Voltage Generation

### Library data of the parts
C27 C28 C30 C33 C34 C52 = GRM188R71E105KA12D: CAP, CERM, 1 µF, 25 V, +/- 10%, X7R, 0603; Manufacturer: MuRata; Polarized: N; CompType: Capacitor; Value: 1uF; U/M: EA; Cap_F: 0.000001; Tolerance_%: 10; Value1: Unknown; VDC_V: 25; Value2: 25V; TaMin_C: -55; TaMax_C: 125; AEC Category: Q200
C29 C32 C35 C38 C40 C42 = C1608X5R1E106M080AC: CAP, CERM, 10 µF, 25 V, +/- 20%, X5R, 0603; Manufacturer: TDK; Polarized: N; CompType: Capacitor; Value: 10uF; U/M: EA; Cap_F: 0.00001; Tolerance_%: 20; ESR_ohm: 0.004639; Value1: 0.004639 ohm; VDC_V: 25; Value2: 25V; IRMS_A: 2.41407; TaMin_C: -55; TaMax_C: 85; SizeArea_mm2: 1.28; SizeAreaWB_mm2: 4.68; SizeX_mm: 1.6; SizeY_mm: 0.8; SizeZ_mm: 1; AEC Category: Q200
C31 C39 C41 C44 = C0603C104J3RACTU: CAP, CERM, 0.1 µF, 25 V, +/- 5%, X7R, 0603; Manufacturer: Kemet; Polarized: N; CompType: Capacitor; Value: 0.1uF; U/M: EA; Cap_F: 0.0000001; Tolerance_%: 5; Value1: Unknown; VDC_V: 25; Value2: 25V; TaMin_C: -55; TaMax_C: 125; AEC Category: Q200
J4 J5 = 901-144-8RFX: SMA Straight Jack, Gold, 50 Ohm, TH; Manufacturer: Amphenol RF; SymbolCreator: X0208326
L2 = UPZ2012E102-1R5TF: FERRITE BEAD 1 KOHM 0805 1LN; Manufacturer: TDK Corporation; Imax_A: 1.5; DCR_ohm: 0.12; Value1: 0.12 ohm; Value2: 1.5A; ZTyp@100MHz_Ohm: 1000
R17 R24 R25 = RT0603DRE071KL: RES, 1.00 k, 0.5%, 0.1 W, 0603; Manufacturer: Yageo America; CompType: Resistor; Value: 1.00k; Res_ohm: 1000; Value_Code: 1k00; Tolerance_%: 0.5; Power_W: 0.1; Value2: 0.1W; VDC_V: 75; TempCo: 50 ppm/C; SizeArea_mm2: 1.28; SizeX_mm: 1.6; SizeY_mm: 0.8; SizeZ_mm: 1; EIA_Code: E192; U/M: EA; AEC Category: Q200
R18 R20-R23 R31 R54 = CRCW06030000Z0EA: as R1 on sheet TIDA-01427_Power_Supply
R19 = CRCW06031R00FKEA: RES, 1.00, 1%, 0.1 W, 0603; Manufacturer: Vishay-Dale; CompType: Resistor; Value: 1.00; Res_ohm: 1; Value_Code: 1R00; Power_W: 0.1; Value2: 0.1W; VDC_V: 75; TempCo: 100 ppm/C; SizeArea_mm2: 1.28; SizeX_mm: 1.6; SizeY_mm: 0.8; EIA_Code: E96; U/M: EA; AEC Category: Q200
R29 = RT0603DRE074K02L: RES, 4.02 k, 0.5%, 0.1 W, 0603; Manufacturer: Yageo America; CompType: Resistor; Value: 4.02k; Res_ohm: 4020; Value_Code: 4k02; Tolerance_%: 0.5; Power_W: 0.1; Value2: 0.1W; VDC_V: 75; TempCo: 50 ppm/C; SizeArea_mm2: 1.28; SizeX_mm: 1.6; SizeY_mm: 0.8; SizeZ_mm: 1; EIA_Code: E192; U/M: EA; AEC Category: Q200
R33 = RT0603DRE07374RL: RES, 374, 0.5%, 0.1 W, 0603; Manufacturer: Yageo America; CompType: Resistor; Value: 374; Value_Code: 374R; Tolerance_%: 0.5; Power_W: 0.1; Value2: 0.1W; VDC_V: 75; TempCo: 50 ppm/C; SizeArea_mm2: 1.28; SizeX_mm: 1.6; SizeY_mm: 0.8; SizeZ_mm: 1; EIA_Code: E192; U/M: EA; AEC Category: Q200
R56 = RT0603DRE07590RL: RES, 590, 0.5%, 0.1 W, 0603; Manufacturer: Yageo America; CompType: Resistor; Value: 590; Value_Code: 590R; Tolerance_%: 0.5; Power_W: 0.1; Value2: 0.1W; VDC_V: 75; TempCo: 50 ppm/C; SizeArea_mm2: 1.28; SizeX_mm: 1.6; SizeY_mm: 0.8; SizeZ_mm: 1; EIA_Code: E192; U/M: EA; AEC Category: Q200
REF_N10V_B REF_P10V REF_P10V_B VOCM = 5007: as GND on sheet TIDA-01427_Power_Supply
U4 = REF5010AIDGKR: Low Noise, Very Low Drift, Precision Voltage Reference, -40 to 125 degC, 8-pin MSOP (DGK), Green (RoHS & no Sb/Br); Manufacturer: Texas Instruments; Alternate PartNumber: Equivalent; Initial Accuracy @ 25/deg C(%): 0.05; Iout/Iz(Max)(mA): 10; Iq(Max)(uA): 1000; Rating: Catalog; SubFamily: Series Voltage Reference; Temp Coeff(Max)(ppm/ degree C): 3; VI(Max)(V): 18; VI(Min)(V): 10.2
U5 = OPA2209AIDGKR: 2.2 nV/rtHz, 18 MHz, Precision, RRO, Operational Amplifier, 4.5 to 36 V, -40 to 125 degC, 8-pin SOP (DGK0008A), Green (RoHS & no Sb/Br); Manufacturer: Texas Instruments; Alternate PartNumber: Equivalent; CMRR(Min)(dB): 120; GBW(Typ)(MHz): 18; IIB(Max)(pA): 4500; Iq per channel(Max)(mA): 2.5; Number of Channels: 2; Offset Drift(Typ)(uV/C): 1; Packing: LARGE T&R; Rating: Catalog; Slew Rate(Typ)(V/us): 6.4; Sub Family: High Supply Voltage Amplifier (>=30V), Low Noise Amp (<=10nV/rtHz), Low Offset Voltage Amplifier (<=500uV), Precision Amplifier; Total Supply Voltage(Max)(+5V is 5, +/-5V is 10): 36; Total Supply Voltage(Min)(+5V is 5, +/-5V is 10): 4.5; Vio (25C)(Max)(mV): 0.15

## Sheet TIDA-01427_DAC_I2V_Filter_Attenuator.SchDoc: Signal Chain
size 431 x 279 mm; Date: Not shown in title block; ApprovedBy: Not shown in title block; CheckedBy: Not shown in title block; Author: Not shown in title block; CompanyName: Not shown in title block; DrawnBy: Sanjay Pithadia; Engineer: Not shown in title block; Organization: Not shown in title block; Address1: Not shown in title block; Address2: Not shown in title block; Address3: Not shown in title block; Address4: Not shown in title block; DocumentNumber: 1; Revision: Use project parameter SCH_Rev; SheetNumber: 4; SheetTotal: 5; PageSetup: Record=PageOptions¦CenterHorizontal=True¦CenterVertical=True¦PrintScale=1.00¦XCorrection=1.00¦YCorrection=1.00¦PrintKind=0¦BorderSize=5000000¦LeftOffset=0¦BottomOffset=0¦Orientation=2¦PaperLength=1000¦PaperWidth=1000¦Scale=100¦PaperSource=15¦PrintQuality=600¦MediaType=1¦DitherType=10¦PaperKind=Letter¦PrintScaleMode=1
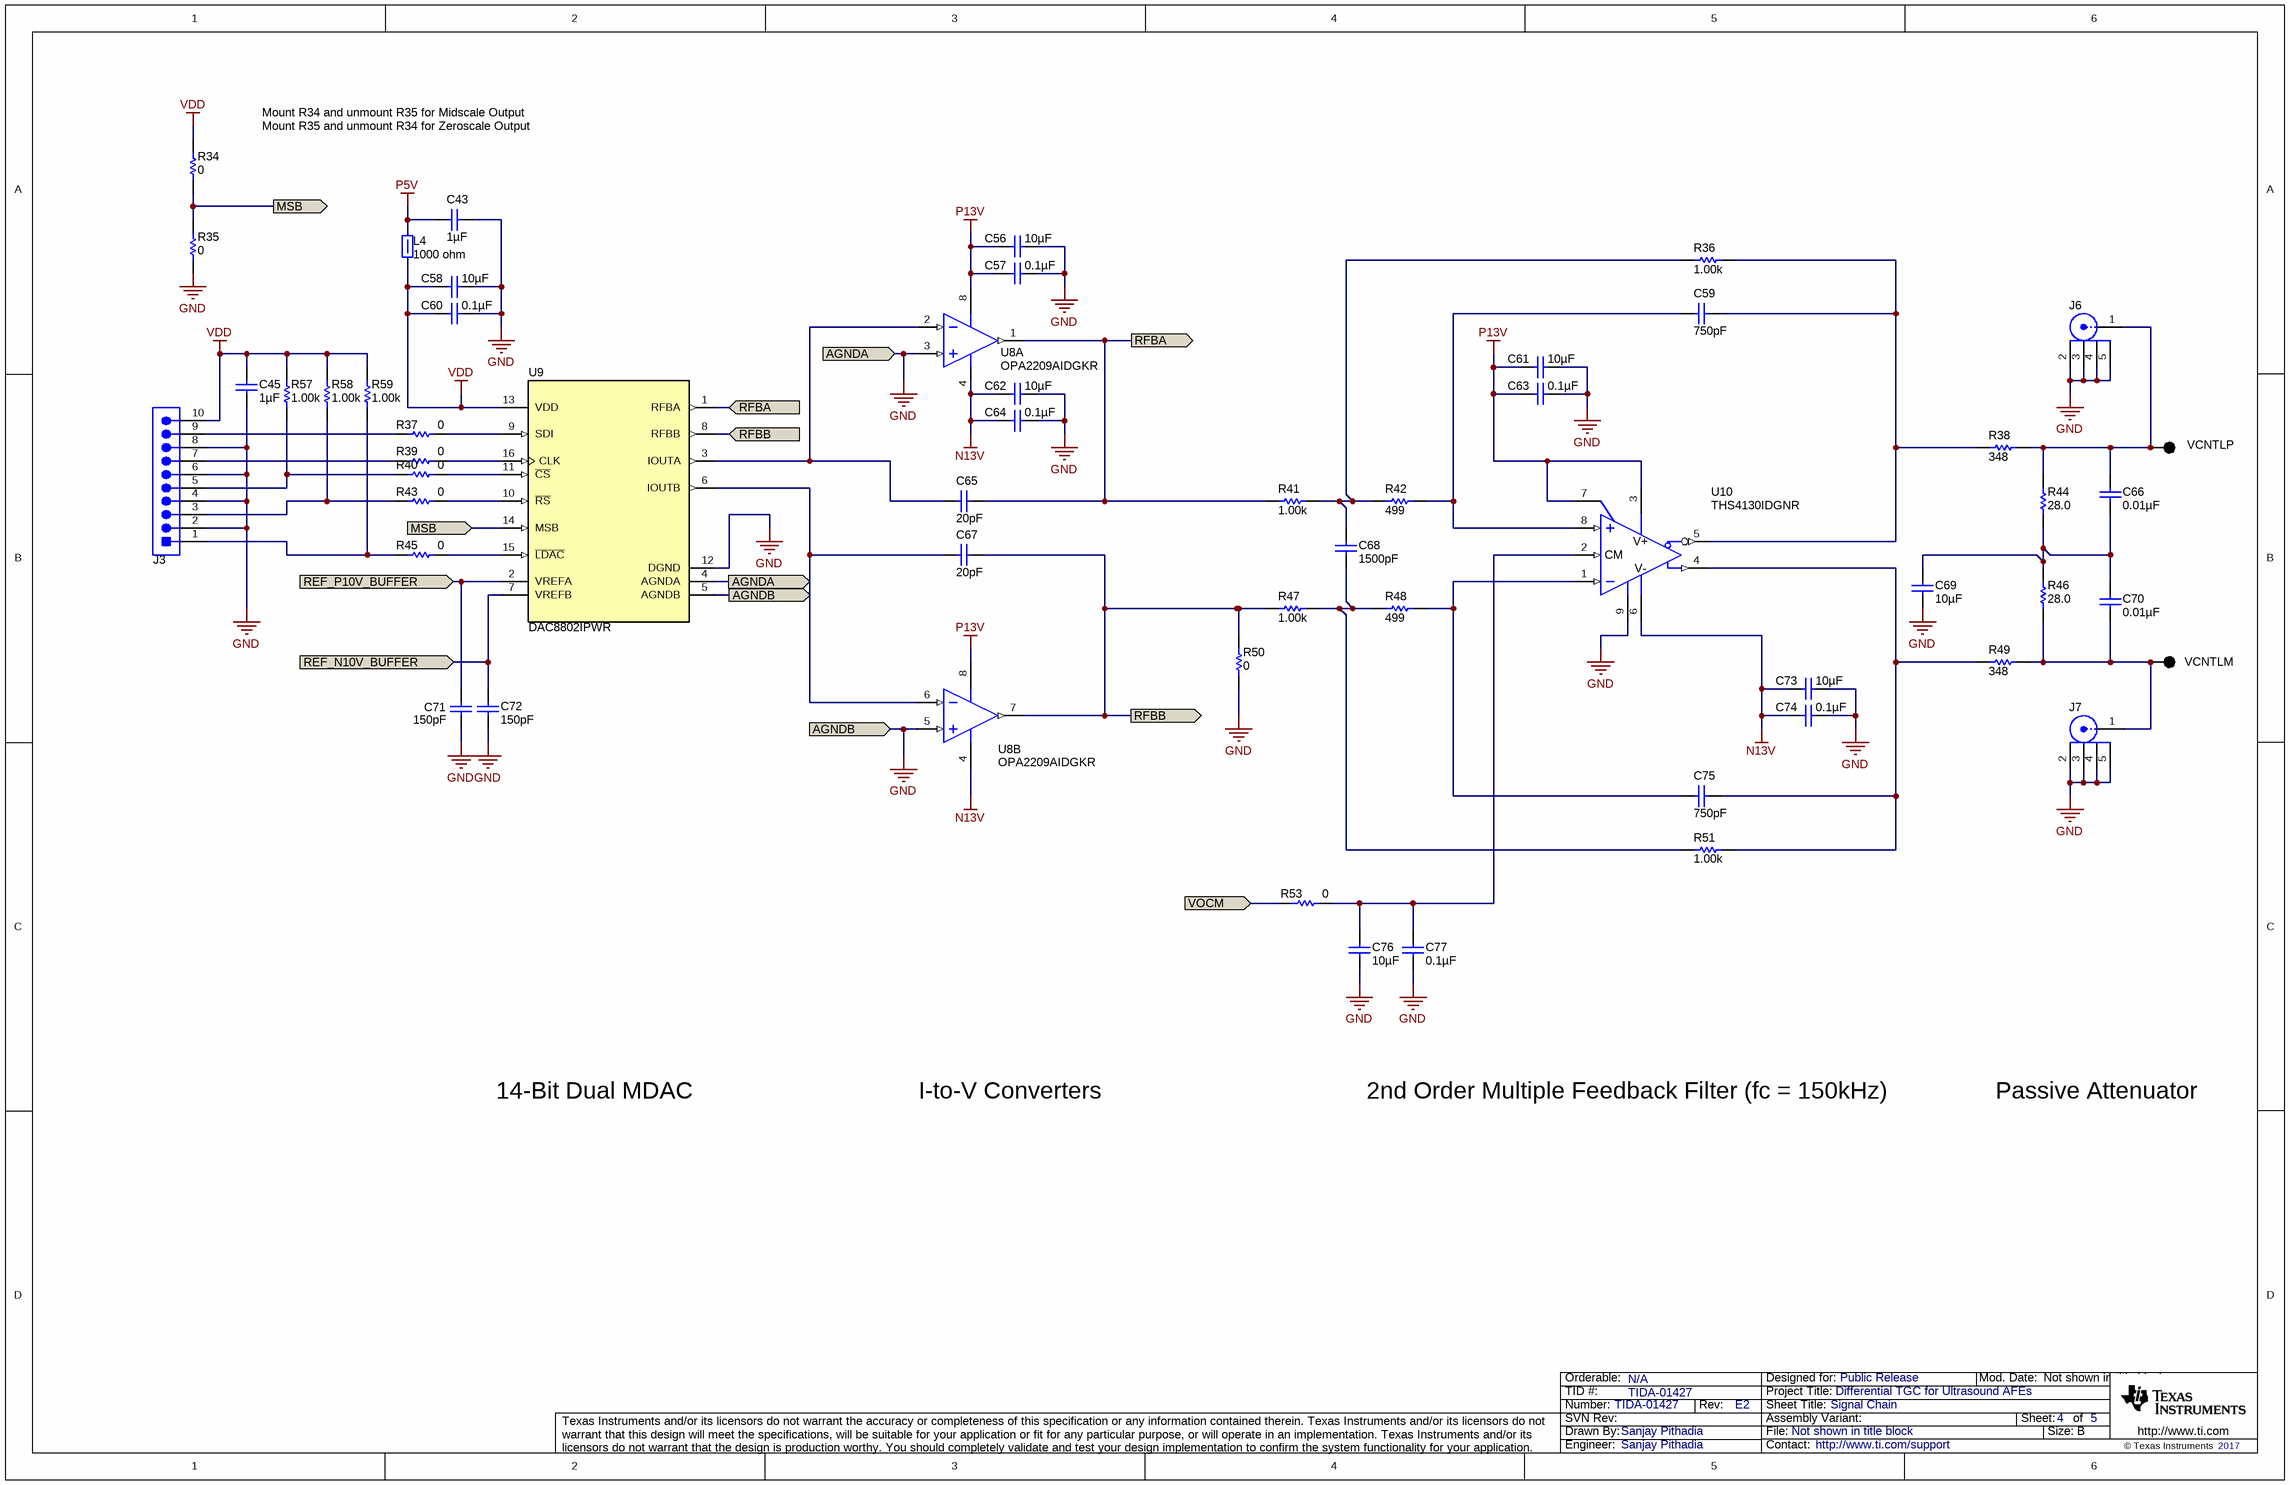
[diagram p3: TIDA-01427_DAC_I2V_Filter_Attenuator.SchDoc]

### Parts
C43  ValueDisplayed: 1µF  [0603]  (hidden comment: GRM188R71E105KA12D)
C45  ValueDisplayed: 1µF  [0603]  (hidden comment: GRM188R71E105KA12D)
C56  ValueDisplayed: 10µF  [0603]  (hidden comment: C1608X5R1E106M080AC)
C57  ValueDisplayed: 0.1µF  [0603]  (hidden comment: C0603C104J3RACTU)
C58  ValueDisplayed: 10µF  [0603]  (hidden comment: C1608X5R1E106M080AC)
C59  ValueDisplayed: 750pF  [0603]  (hidden comment: C0603C751J5GACTU)
C60  ValueDisplayed: 0.1µF  [0603]  (hidden comment: C0603C104J3RACTU)
C61  ValueDisplayed: 10µF  [0603]  (hidden comment: C1608X5R1E106M080AC)
C62  ValueDisplayed: 10µF  [0603]  (hidden comment: C1608X5R1E106M080AC)
C63  ValueDisplayed: 0.1µF  [0603]  (hidden comment: C0603C104J3RACTU)
C64  ValueDisplayed: 0.1µF  [0603]  (hidden comment: C0603C104J3RACTU)
C65  ValueDisplayed: 20pF  [0805_HV]  (hidden comment: GQM2195C1H200JB01D)
C66  ValueDisplayed: 0.01µF  [0603]  (hidden comment: GRM188R71H103KA01D)
C67  ValueDisplayed: 20pF  [0805_HV]  (hidden comment: GQM2195C1H200JB01D)
C68  ValueDisplayed: 1500pF  [0805_HV]  (hidden comment: 08055A152JAT2A)
C69  ValueDisplayed: 10µF  [0805_HV]  (hidden comment: 0805YD106KAT2A)
C70  ValueDisplayed: 0.01µF  [0603]  (hidden comment: GRM188R71H103KA01D)
C71  ValueDisplayed: 150pF  [0603]  (hidden comment: 06035A151JAT2A)
C72  ValueDisplayed: 150pF  [0603]  (hidden comment: 06035A151JAT2A)
C73  ValueDisplayed: 10µF  [0603]  (hidden comment: C1608X5R1E106M080AC)
C74  ValueDisplayed: 0.1µF  [0603]  (hidden comment: C0603C104J3RACTU)
C75  ValueDisplayed: 750pF  [0603]  (hidden comment: C0603C751J5GACTU)
C76  ValueDisplayed: 10µF  [0805_HV]  (hidden comment: 0805YD106KAT2A)
C77  ValueDisplayed: 0.1µF  [0603]  (hidden comment: C0603C104J3RACTU)
J3  61301011121  [Wurth_61301011121]  (value not drawn)
J6  901-144-8RFX  [Amphenol_901-144-8RFX]  (value not drawn)
J7  901-144-8RFX  [Amphenol_901-144-8RFX]  (value not drawn)
L4  value 1000 ohm  [0805_HV]  (hidden comment: MPZ2012S102AT000)
R34  ValueDisplayed: 0  [0603]  (hidden comment: CRCW06030000Z0EA)
R35  ValueDisplayed: 0  [0603]  (hidden comment: CRCW06030000Z0EA)
R36  ValueDisplayed: 1.00k  [0603]  (hidden comment: RT0603DRE071KL)
R37  ValueDisplayed: 0  [0603]  (hidden comment: CRCW06030000Z0EA)
R38  ValueDisplayed: 348  [2010]  (hidden comment: CRCW2010348RFKEF)
R39  ValueDisplayed: 0  [0603]  (hidden comment: CRCW06030000Z0EA)
R40  ValueDisplayed: 0  [0603]  (hidden comment: CRCW06030000Z0EA)
R41  ValueDisplayed: 1.00k  [0603]  (hidden comment: RT0603DRE071KL)
R42  ValueDisplayed: 499  [0603]  (hidden comment: RT0603DRE07499RL)
R43  ValueDisplayed: 0  [0603]  (hidden comment: CRCW06030000Z0EA)
R44  ValueDisplayed: 28.0  [1206]  (hidden comment: RT1206DRD0728RL)
R45  ValueDisplayed: 0  [0603]  (hidden comment: CRCW06030000Z0EA)
R46  ValueDisplayed: 28.0  [1206]  (hidden comment: RT1206DRD0728RL)
R47  ValueDisplayed: 1.00k  [0603]  (hidden comment: RT0603DRE071KL)
R48  ValueDisplayed: 499  [0603]  (hidden comment: RT0603DRE07499RL)
R49  ValueDisplayed: 348  [2010]  (hidden comment: CRCW2010348RFKEF)
R50  ValueDisplayed: 0  [0603]  (hidden comment: CRCW06030000Z0EA)
R51  ValueDisplayed: 1.00k  [0603]  (hidden comment: RT0603DRE071KL)
R53  ValueDisplayed: 0  [0603]  (hidden comment: CRCW06030000Z0EA)
R57  ValueDisplayed: 1.00k  [0603]  (hidden comment: RT0603DRE071KL)
R58  ValueDisplayed: 1.00k  [0603]  (hidden comment: RT0603DRE071KL)
R59  ValueDisplayed: 1.00k  [0603]  (hidden comment: RT0603DRE071KL)
U8  OPA2209AIDGKR  [DGK0008A_N]  (parts A,B of 2)
U9  DAC8802IPWR  [PW0016A_N]
U10  THS4130IDGNR  [DGN0008D_N]
VCNTLM  5001  [Keystone5001]  (value not drawn)
VCNTLP  5001  [Keystone5001]  (value not drawn)

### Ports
AGNDA (in), AGNDA (out), AGNDB (in), AGNDB (out), MSB (in), MSB (out), REF_N10V_BUFFER (in), REF_P10V_BUFFER (in), RFBA (in), RFBA (out), RFBB (in), RFBB (out), VOCM (in)

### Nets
GND: C43.2 C45.2 C56.2 C57.1 C58.2 C60.1 C61.2 C62.2 C63.1 C64.1 C67.2 C69.2 C71.2 C72.2 C73.2 C74.1 C76.2 C77.2 J3.2 J3.4 J3.6 J3.8 J6.2 J6.3 J6.4 J6.5 J7.2 J7.3 J7.4 J7.5 R35.1 R50.1 U8.3(IN_A+) U8.5(IN_B+) U8.6(IN_B-) U9.4(AGNDA) U9.5(AGNDB) U9.6(IOUTB) U9.12(DGND) U10.9(PAD) ; port AGNDA, port AGNDB
N13V: C62.1 C64.2 C73.1 C74.2 U8.4(V-) U10.6(VCC-)
P5V: C43.1 L4.2
P13V: C56.1 C57.2 C61.1 C63.2 U8.8(V+) U10.3(VCC+) U10.7(NC)
VDD: C45.1 C58.1 C60.2 J3.10 L4.1 R34.2 R57.2 R58.2 R59.2 U9.13(VDD)
MSB: R34.1 R35.2 U9.14(MSB) ; port MSB
REF_N10V_Buffer: C72.1 U9.7(VREFB) ; port REF_N10V_BUFFER
REF_P10V_Buffer: C71.1 U9.2(VREFA) ; port REF_P10V_BUFFER
RFBA: C65.1 R41.1 U8.1(OUT_A) U9.1(RFBA) ; port RFBA
RFBB: C67.1 R47.1 R50.2 U8.7(OUT_B) U9.8(RFBB) ; port RFBB
VOCM: R53.1 ; port VOCM
NetC59_1: C59.1 R36.2 R38.1 U10.5(VOUT-)
NetC59_2: C59.2 R42.2 U10.8(VIN+)
NetC65_2: C65.2 U8.2(IN_A-) U9.3(IOUTA)
NetC66_1: C66.1 J6.1 R38.2 R44.2 VCNTLP.1
NetC66_2: C66.2 C69.1 C70.1 R44.1 R46.2
NetC68_1: C68.1 R36.1 R41.2 R42.1
NetC68_2: C68.2 R47.2 R48.1 R51.1
NetC70_2: C70.2 J7.1 R46.1 R49.2 VCNTLM.1
NetC75_1: C75.1 R49.1 R51.2 U10.4(VOUT+)
NetC75_2: C75.2 R48.2 U10.1(VIN-)
NetC76_1: C76.1 C77.1 R53.2 U10.2(VOCM)
NetJ3_1: J3.1 R45.1 R59.1
NetJ3_3: J3.3 R43.1 R58.1
NetJ3_5: J3.5 R40.1 R57.1
NetJ3_7: J3.7 R39.1
NetJ3_9: J3.9 R37.1
NetR37_2: R37.2 U9.9(SDI)
NetR39_2: R39.2 U9.16(CLK)
NetR40_2: R40.2 U9.11(~{CS})
NetR43_2: R43.2 U9.10(~{RS})
NetR45_2: R45.2 U9.15(~{LDAC})

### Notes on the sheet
- Mount R34 and unmount R35 for Midscale Output
- Mount R35 and unmount R34 for Zeroscale Output
- 14-Bit Dual MDAC
- I-to-V Converters
- 2nd Order Multiple Feedback Filter (fc = 150kHz)
- Passive Attenuator

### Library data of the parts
C43 C45 = GRM188R71E105KA12D: as C27 on sheet TIDA-01427_Reference
C56 C58 C61 C62 C73 = C1608X5R1E106M080AC: as C29 on sheet TIDA-01427_Reference
C57 C60 C63 C64 C74 C77 = C0603C104J3RACTU: as C31 on sheet TIDA-01427_Reference
C59 C75 = C0603C751J5GACTU: CAP, CERM, 750 pF, 50 V, +/- 5%, C0G/NP0, 0603; Manufacturer: Kemet; Polarized: N; CompType: Capacitor; Value: 750pF; U/M: EA; Cap_F: 0.00000000075; Tolerance_%: 5; Value1: Unknown; VDC_V: 50; Value2: 50V; TaMin_C: -55; TaMax_C: 125; SizeArea_mm2: 1.28; SizeAreaWB_mm2: 4.68; SizeX_mm: 1.6; SizeY_mm: 0.8; SizeZ_mm: 1; AEC Category: Q200
C65 C67 = GQM2195C1H200JB01D: CAP, CERM, 20 pF, 50 V, +/- 5%, C0G/NP0, 0805; Manufacturer: MuRata; Polarized: N; CompType: Capacitor; Value: 20pF; U/M: EA; Cap_F: 0.00000000002; Tolerance_%: 5; Value1: Unknown; VDC_V: 50; Value2: 50V; TaMin_C: -55; TaMax_C: 125; Cap_Case: 0805; SizeArea_mm2: 2.5; SizeAreaWB_mm2: 6.75; SizeX_mm: 2; SizeY_mm: 1.25; SizeZ_mm: 1.45; AEC Category: Q200
C66 C70 = GRM188R71H103KA01D: CAP, CERM, 0.01 µF, 50 V, +/- 10%, X7R, 0603; Manufacturer: MuRata; Polarized: N; CompType: Capacitor; Value: 0.01uF; U/M: EA; Cap_F: 0.00000001; Tolerance_%: 10; Value1: Unknown; VDC_V: 50; Value2: 50V; TaMin_C: -55; TaMax_C: 125; SizeArea_mm2: 1.28; SizeAreaWB_mm2: 4.68; SizeX_mm: 1.6; SizeY_mm: 0.8; SizeZ_mm: 1; AEC Category: Q200
C68 = 08055A152JAT2A: CAP, CERM, 1500 pF, 50 V, +/- 5%, C0G/NP0, 0805; Manufacturer: AVX; Polarized: N; CompType: Capacitor; Value: 1500pF; U/M: EA; Cap_F: 0.0000000015; Tolerance_%: 5; ESR_ohm: 0.094; Value1: 0.094 ohm; VDC_V: 50; Value2: 50V; TaMin_C: -55; TaMax_C: 125; Cap_Case: 0805; SizeArea_mm2: 2.5; SizeAreaWB_mm2: 6.75; SizeX_mm: 2; SizeY_mm: 1.25; SizeZ_mm: 1.45; AEC Category: Q200
C69 C76 = 0805YD106KAT2A: CAP, CERM, 10 µF, 16 V, +/- 10%, X5R, 0805; Manufacturer: AVX; Polarized: N; CompType: Capacitor; Value: 10uF; U/M: EA; Cap_F: 0.00001; Tolerance_%: 10; Value1: Unknown; VDC_V: 16; Value2: 16V; TaMin_C: -55; TaMax_C: 85; Cap_Case: 0805; SizeArea_mm2: 2.5; SizeAreaWB_mm2: 6.75; SizeX_mm: 2; SizeY_mm: 1.25; SizeZ_mm: 1.45; AEC Category: Q200
C71 C72 = 06035A151JAT2A: CAP, CERM, 150 pF, 50 V, +/- 5%, C0G/NP0, 0603; Manufacturer: AVX; Polarized: N; CompType: Capacitor; Value: 150pF; U/M: EA; Cap_F: 0.00000000015; Tolerance_%: 5; ESR_ohm: 0.098; Value1: 0.098 ohm; VDC_V: 50; Value2: 50V; TaMin_C: -55; TaMax_C: 125; SizeArea_mm2: 1.28; SizeAreaWB_mm2: 4.68; SizeX_mm: 1.6; SizeY_mm: 0.8; SizeZ_mm: 1; AEC Category: Q200
J3 = 61301011121: Header, 2.54mm, 10x1, Gold, TH; Manufacturer: Wurth Elektronik; SymbolCreator: a0412235; Pitch_mm: 2.54; Gender: Male; Shrouded: N; Row_Count: 1
J6 J7 = 901-144-8RFX: as J4 on sheet TIDA-01427_Reference
L4 = UPZ2012E102-1R5TF: as L2 on sheet TIDA-01427_Reference
R34 R35 R37 R39 R40 R43 R45 R50 R53 = CRCW06030000Z0EA: as R1 on sheet TIDA-01427_Power_Supply
R36 R41 R47 R51 R57-R59 = RT0603DRE071KL: as R17 on sheet TIDA-01427_Reference
R38 R49 = CRCW2010348RFKEF: RES, 348, 1%, 0.75 W, AEC-Q200 Grade 0, 2010; Manufacturer: Vishay-Dale; CompType: Resistor; Value: 348; Value_Code: 348R; Tolerance_%: 1; Power_W: 0.75; Value2: 0.75W; VDC_V: 400; TempCo: 100 ppm/C; SizeArea_mm2: 12.5; SizeX_mm: 5; SizeY_mm: 2.5; SizeZ_mm: 1.66; EIA_Code: E96; U/M: EA; AEC Category: Q200; AEC Qualified: Y; AEC Grade: 0
R42 R48 = RT0603DRE07499RL: RES, 499, 0.5%, 0.1 W, 0603; Manufacturer: Yageo America; CompType: Resistor; Value: 499; Value_Code: 499R; Tolerance_%: 0.5; Power_W: 0.1; Value2: 0.1W; VDC_V: 75; TempCo: 50 ppm/C; SizeArea_mm2: 1.28; SizeX_mm: 1.6; SizeY_mm: 0.8; SizeZ_mm: 1; EIA_Code: E192; U/M: EA; AEC Category: Q200
R44 R46 = CRCW120628R0FKEA: RES, 28.0, 0.5%, 0.25 W, 1206; Manufacturer: Yageo; CompType: Resistor; Value: 28.0; Res_ohm: 28; Value_Code: 28R0; Tolerance_%: 1; Power_W: 0.25; Value2: 0.25W; VDC_V: 200; TempCo: 100 ppm/C; SizeArea_mm2: 5.12; SizeX_mm: 3.2; SizeY_mm: 1.6; SizeZ_mm: 1.35; EIA_Code: E96; U/M: EA; AEC Category: Q200
U8 = OPA2209AIDGKR: as U5 on sheet TIDA-01427_Reference
U9 = DAC8802IPWR: Dual, Serial Input 14-Bit Multiplying Digital-to-Analog Converter, PW0016A (TSSOP-16); Manufacturer: Texas Instruments; SymbolCreator: Altium; SizeArea_mm2: 32; SizeAreaWB_mm2: 58.8; SizeX_mm: 6.4; SizeY_mm: 5; SizeZ_mm: 1.2; CompType: IC; U/M: EA
U10 = THS4131IDGNR: Fully Differential Input/Output Low Noise Amplifier, DGN0008D (VSSOP-8); Manufacturer: Texas Instruments; SymbolCreator: Altium; SizeArea_mm2: 15.655; SizeAreaWB_mm2: 35.955; SizeX_mm: 5.05; SizeY_mm: 3.1; SizeZ_mm: 1.1; CompType: IC; U/M: EA
VCNTLM VCNTLP = 5001: Test Point, Miniature, Black, TH; Manufacturer: Keystone; CompType: Test Point Loop; ContactFinish: Silver

## Sheet TIDA-01427_Hardware.SchDoc: Hardware
size 431 x 279 mm; Date: Not shown in title block; ApprovedBy: Not shown in title block; CheckedBy: Not shown in title block; Author: Not shown in title block; CompanyName: Not shown in title block; DrawnBy: Sanjay Pithadia; Engineer: Not shown in title block; Organization: Not shown in title block; Address1: Not shown in title block; Address2: Not shown in title block; Address3: Not shown in title block; Address4: Not shown in title block; DocumentNumber: 1; Revision: Use project parameter SCH_Rev; SheetNumber: 5; SheetTotal: 5; PageSetup: Record=PageOptions¦CenterHorizontal=True¦CenterVertical=True¦PrintScale=1.00¦XCorrection=1.00¦YCorrection=1.00¦PrintKind=0¦BorderSize=5000000¦LeftOffset=0¦BottomOffset=0¦Orientation=2¦PaperLength=1000¦PaperWidth=1000¦Scale=100¦PaperSource=15¦PrintQuality=600¦MediaType=1¦DitherType=10¦PaperKind=Letter¦PrintScaleMode=1
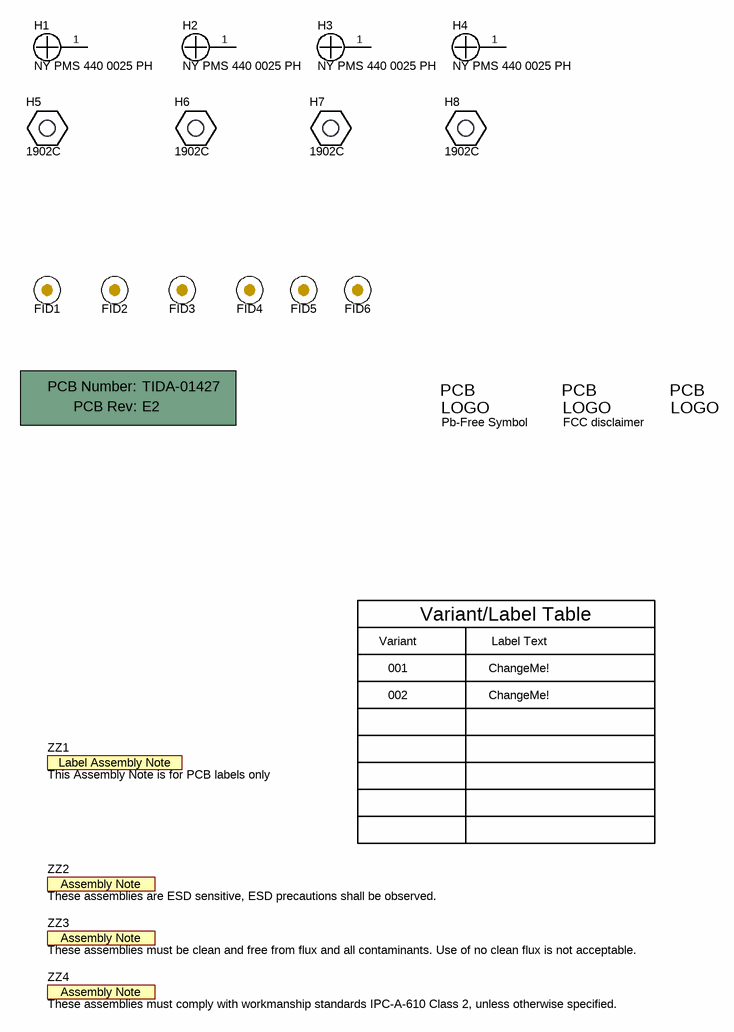
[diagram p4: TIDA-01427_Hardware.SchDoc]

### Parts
!PCB1  Printed Circuit Board  (value not drawn)  (mechanical)
FID1  Fiducial  [Fiducial10-20]  (value not drawn)
FID2  Fiducial  [Fiducial10-20]  (value not drawn)
FID3  Fiducial  [Fiducial10-20]  (value not drawn)
FID4  Fiducial  [Fiducial10-20]  (value not drawn)
FID5  Fiducial  [Fiducial10-20]  (value not drawn)
FID6  Fiducial  [Fiducial10-20]  (value not drawn)
H1  NY PMS 440 0025 PH  [NY PMS 440 0025 PH]
H2  NY PMS 440 0025 PH  [NY PMS 440 0025 PH]
H3  NY PMS 440 0025 PH  [NY PMS 440 0025 PH]
H4  NY PMS 440 0025 PH  [NY PMS 440 0025 PH]
H5  1902C  [Keystone_1902C]
H6  1902C  [Keystone_1902C]
H7  1902C  [Keystone_1902C]
H8  1902C  [Keystone_1902C]
Logo2  Pb-Free Symbol  [Pb-Free_Overlay_Small]  (no BOM)
Logo3  FCC disclaimer  [FCC_disclaimer]  (no BOM)
Logo4  ESD Susceptible  [ESD_Overlay_Small]  (value not drawn)  (no BOM)
ZZ1  This Assembly Note is for PCB labels only  [AssemblyNoteLabel]  (no BOM)
ZZ2  These assemblies are ESD sensitive, ESD precautions shall be observed.  [AssemblyNote]  (no BOM)
ZZ3  These assemblies must be clean and free from flux and all contaminants. Use of no clean flux is not acceptable.  [AssemblyNote]  (no BOM)
ZZ4  These assemblies must comply with workmanship standards IPC-A-610 Class 2, unless otherwise specified.  [AssemblyNote]  (no BOM)

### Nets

Not connected (* = marked no-connect by the designer): H1 1; H2 1; H3 1; H4 1

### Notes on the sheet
- Variant
- Variant/Label Table
- Label Text
- 001
- 002
- ChangeMe!

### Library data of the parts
!PCB1 = PCB: Manufacturer: Any; PartNumber: TIDA-01427; SymbolCreator: a0412235
FID1-FID6 = Fiducial: Fiducial mark.  There is nothing to buy or mount.; SymbolCreator: codlsc
H1-H4 = NY PMS 440 0025 PH: Machine Screw, Round, #4-40 x 1/4, Nylon, Philips panhead; Manufacturer: B&F Fastener Supply; CompType: Hardware; SymbolCreator: codlsc; U/M: EA
H5-H8 = 1902C: Standoff, Hex, 0.5"L #4-40 Nylon; Manufacturer: Keystone; CompType: Hardware
Logo2 = Pb-Free: SymbolCreator: a0412235
Logo3 = FCC_disclaimer: SymbolCreator: codlsc
Logo4 = ESD_Susceptible: ESD Susceptible Symbol; SymbolCreator: a0412235
ZZ1 = AssemblyNoteLabel: SymbolCreator: a0412235
ZZ2-ZZ4 = AssemblyNote: SymbolCreator: codlsc

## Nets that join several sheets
GND: TIDA-01427_Power_Supply (32 pins), TIDA-01427_Reference (24 pins), TIDA-01427_DAC_I2V_Filter_Attenuator (40 pins)
N13V: TIDA-01427_Power_Supply (5 pins), TIDA-01427_Reference (C42.1 C44.2 U5.4), TIDA-01427_DAC_I2V_Filter_Attenuator (6 pins)
P5V: TIDA-01427_Power_Supply (7 pins), TIDA-01427_DAC_I2V_Filter_Attenuator (C43.1 L4.2)
P13V: TIDA-01427_Power_Supply (5 pins), TIDA-01427_Reference (5 pins), TIDA-01427_DAC_I2V_Filter_Attenuator (7 pins)
REF_N10V_Buffer: TIDA-01427_Reference (J5.1 R23.2 REF_N10V_B.1), TIDA-01427_DAC_I2V_Filter_Attenuator (C72.1 U9.7)
REF_P10V_Buffer: TIDA-01427_Reference (J4.1 R21.2 REF_P10V_B.1), TIDA-01427_DAC_I2V_Filter_Attenuator (C71.1 U9.2)
VOCM: TIDA-01427_Reference (C52.2 R31.2 VOCM.1), TIDA-01427_DAC_I2V_Filter_Attenuator (R53.1)

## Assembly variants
001: not fitted FID1 FID2 FID3 FID4 FID5 FID6 R34 R50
